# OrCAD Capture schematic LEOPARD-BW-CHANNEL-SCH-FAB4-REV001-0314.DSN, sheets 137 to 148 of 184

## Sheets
137 026_CPU1 - DDR4 (CHANNEL A): size A3; title: CPU1 - DDR4 (CHANNEL A)
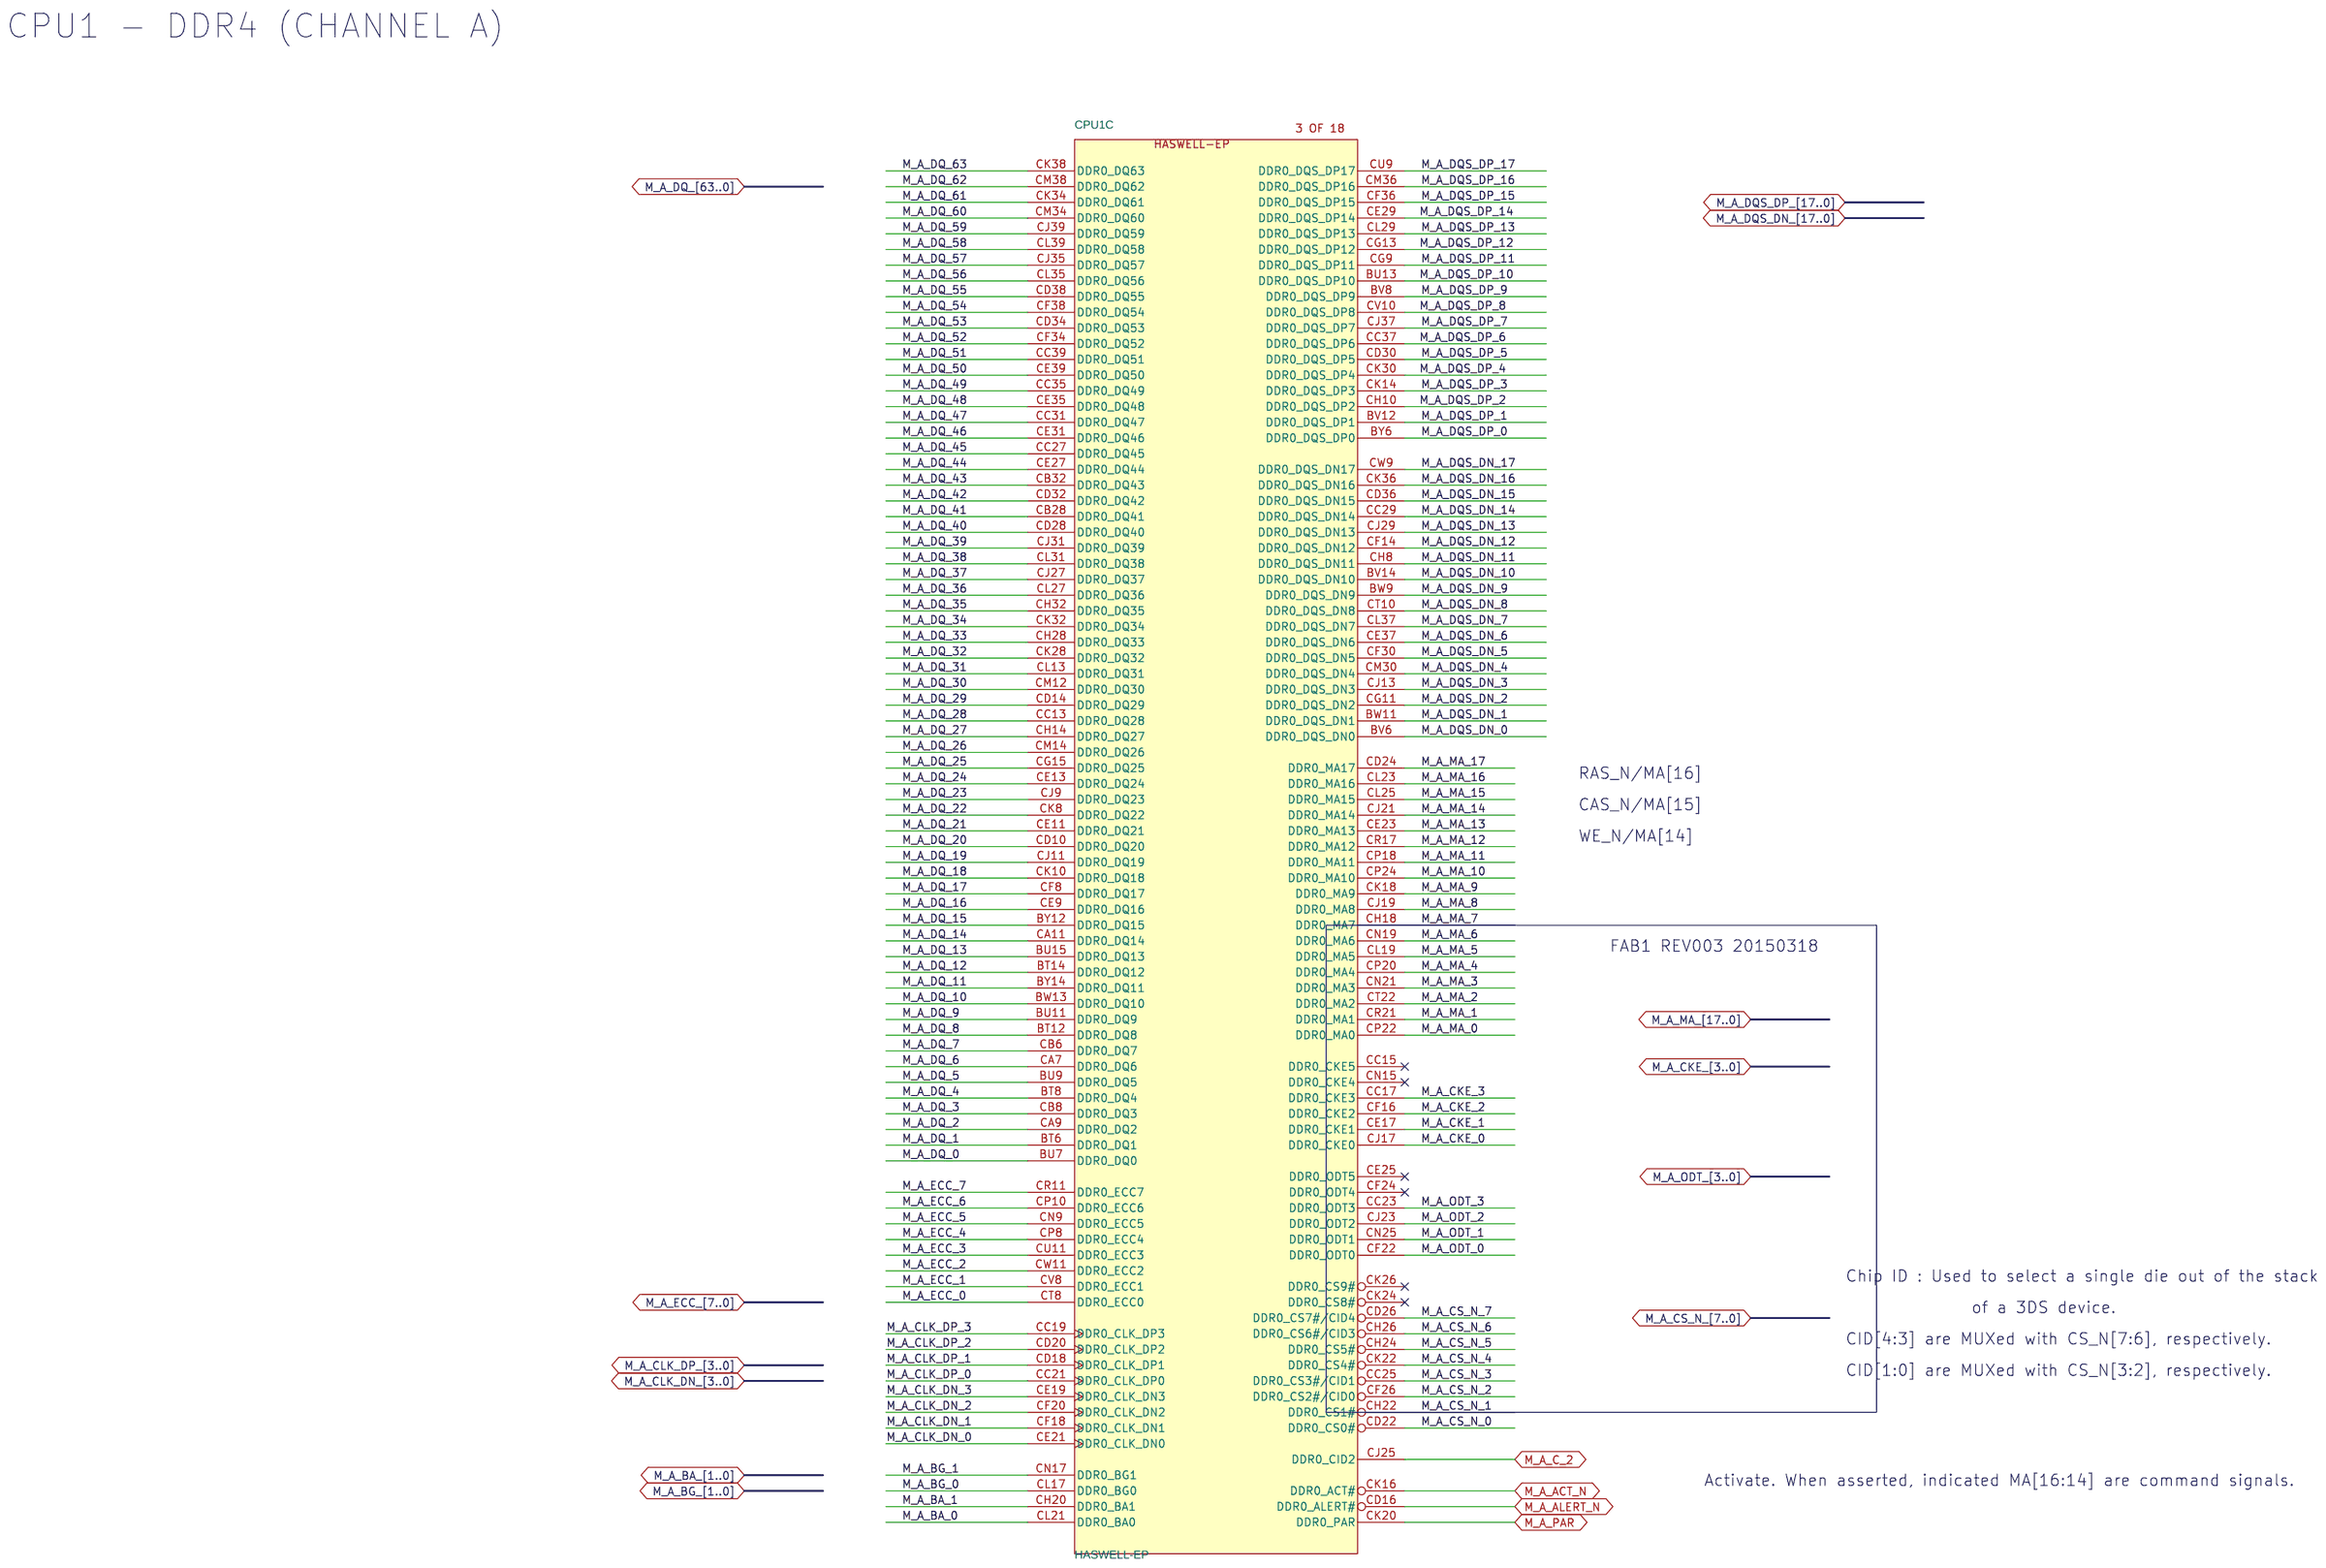
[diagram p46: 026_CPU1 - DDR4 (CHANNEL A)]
138 025_CPU1 - RESERVED PINS: size A3; title: CPU1 - RESERVED PINS
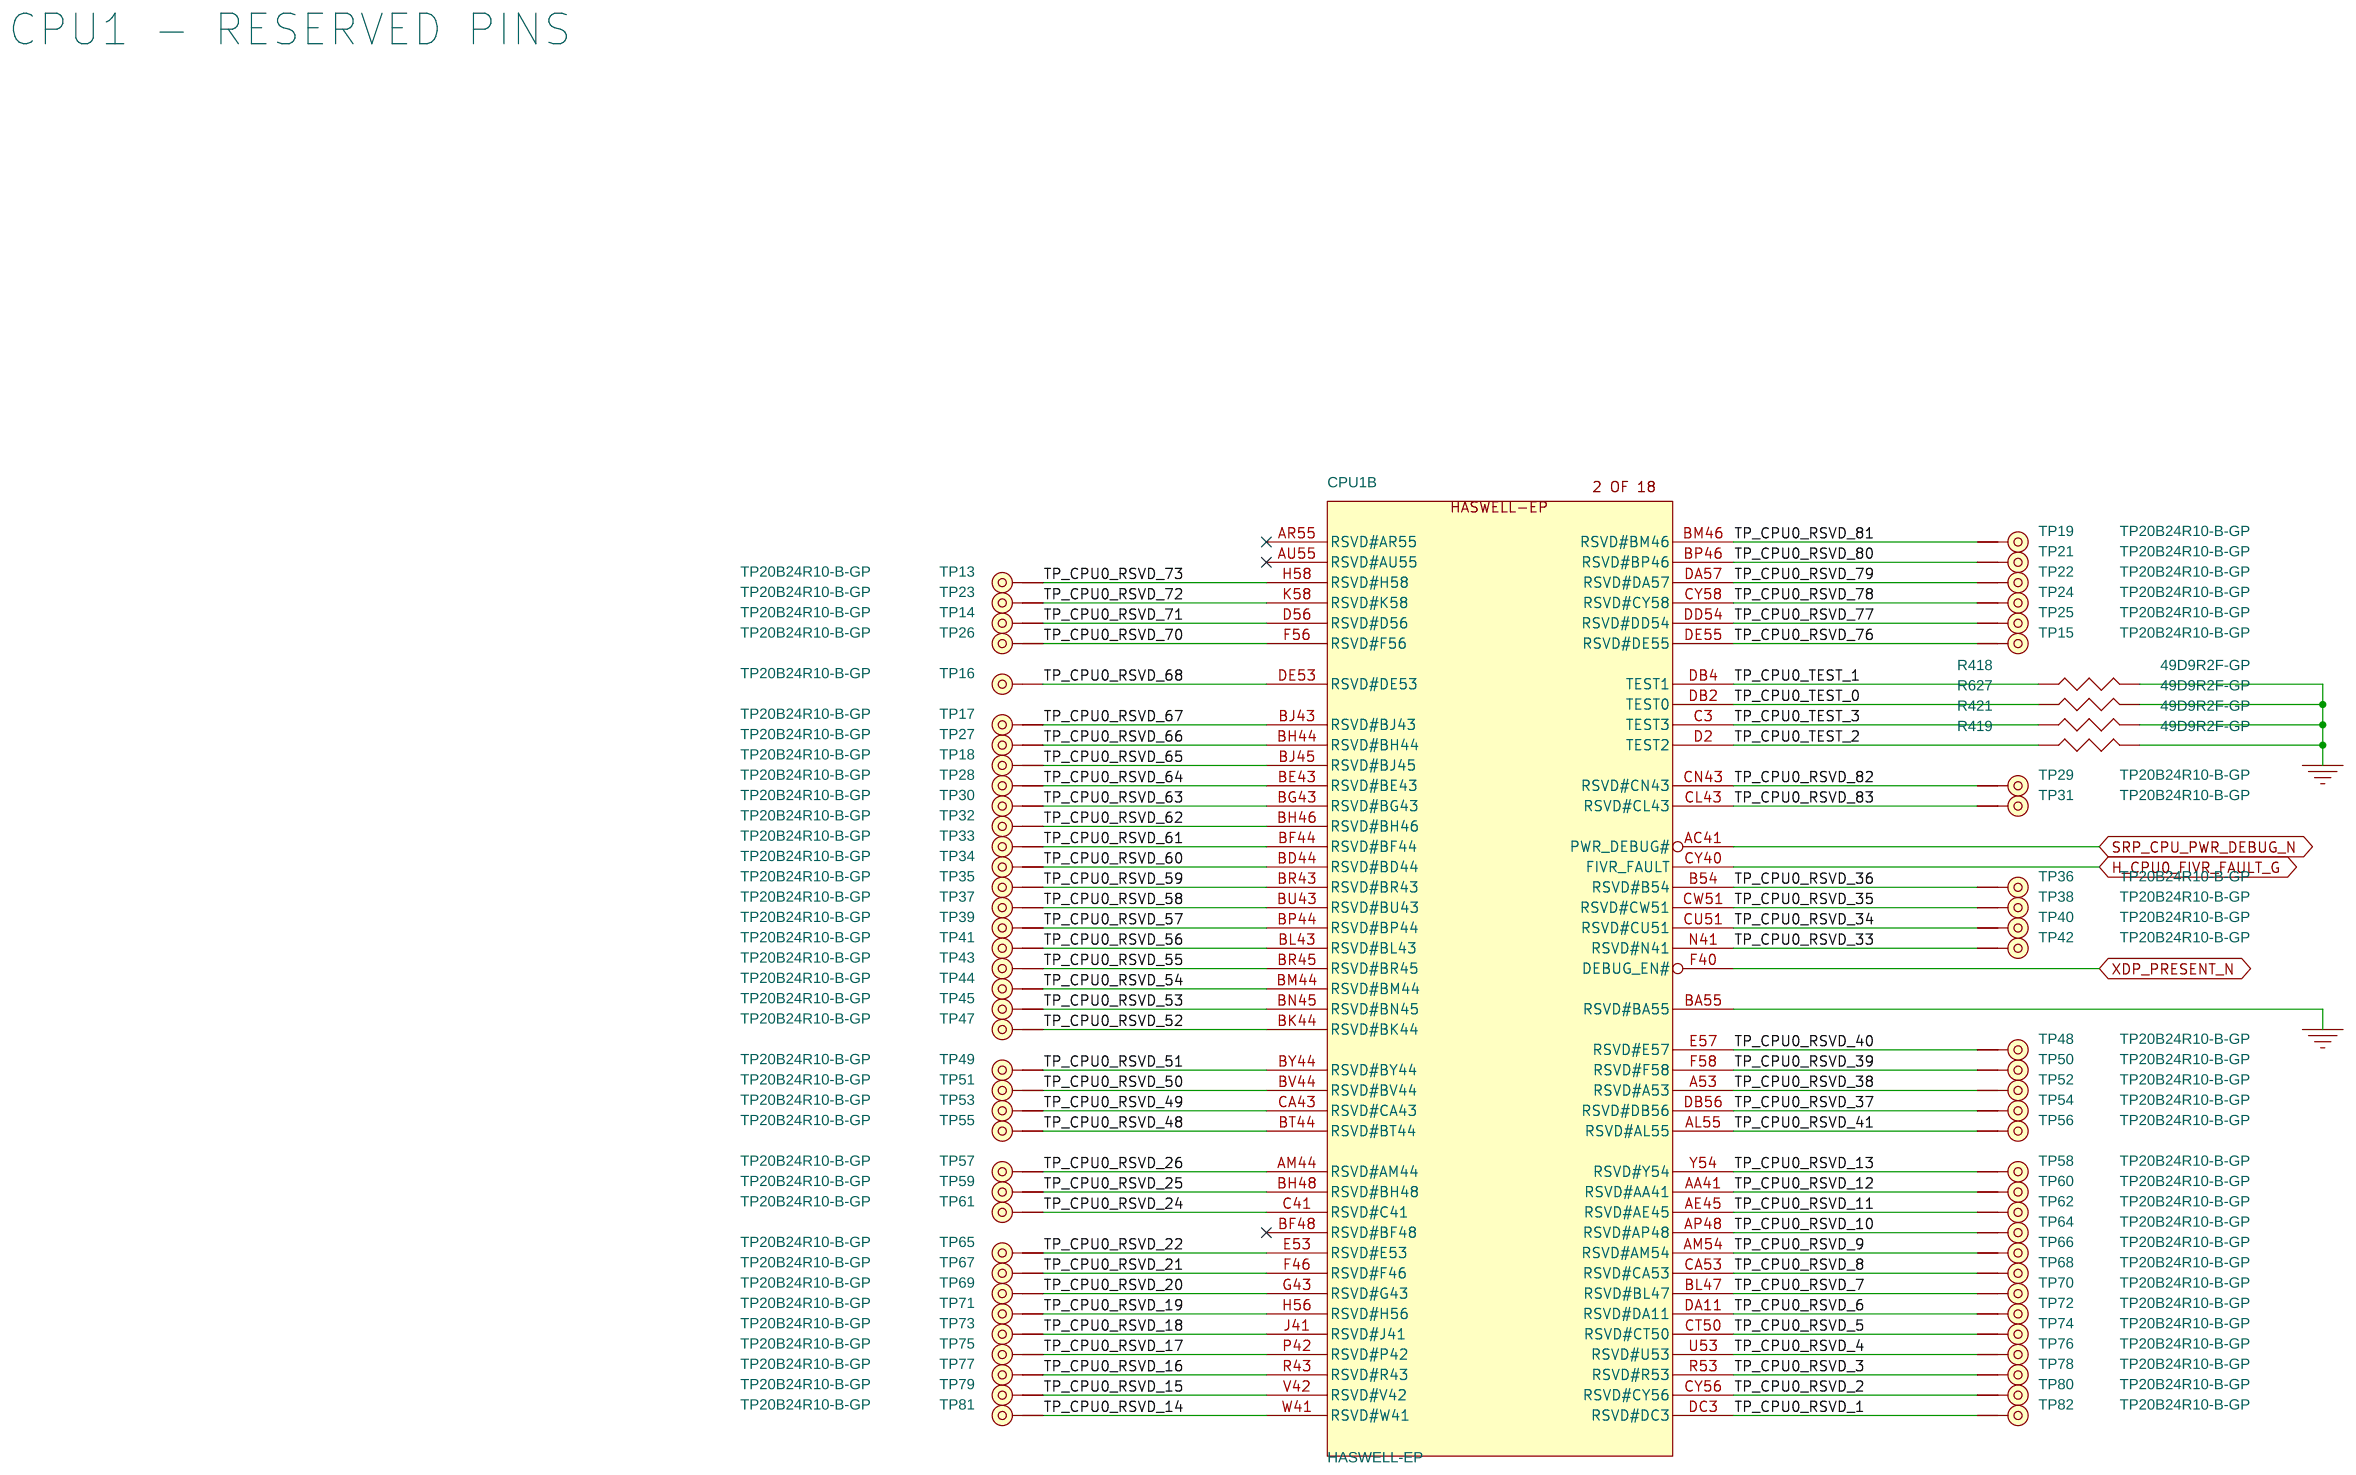
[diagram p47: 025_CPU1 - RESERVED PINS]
139 024_CPU1 - MICS: size A3; title: CPU1 - MICS
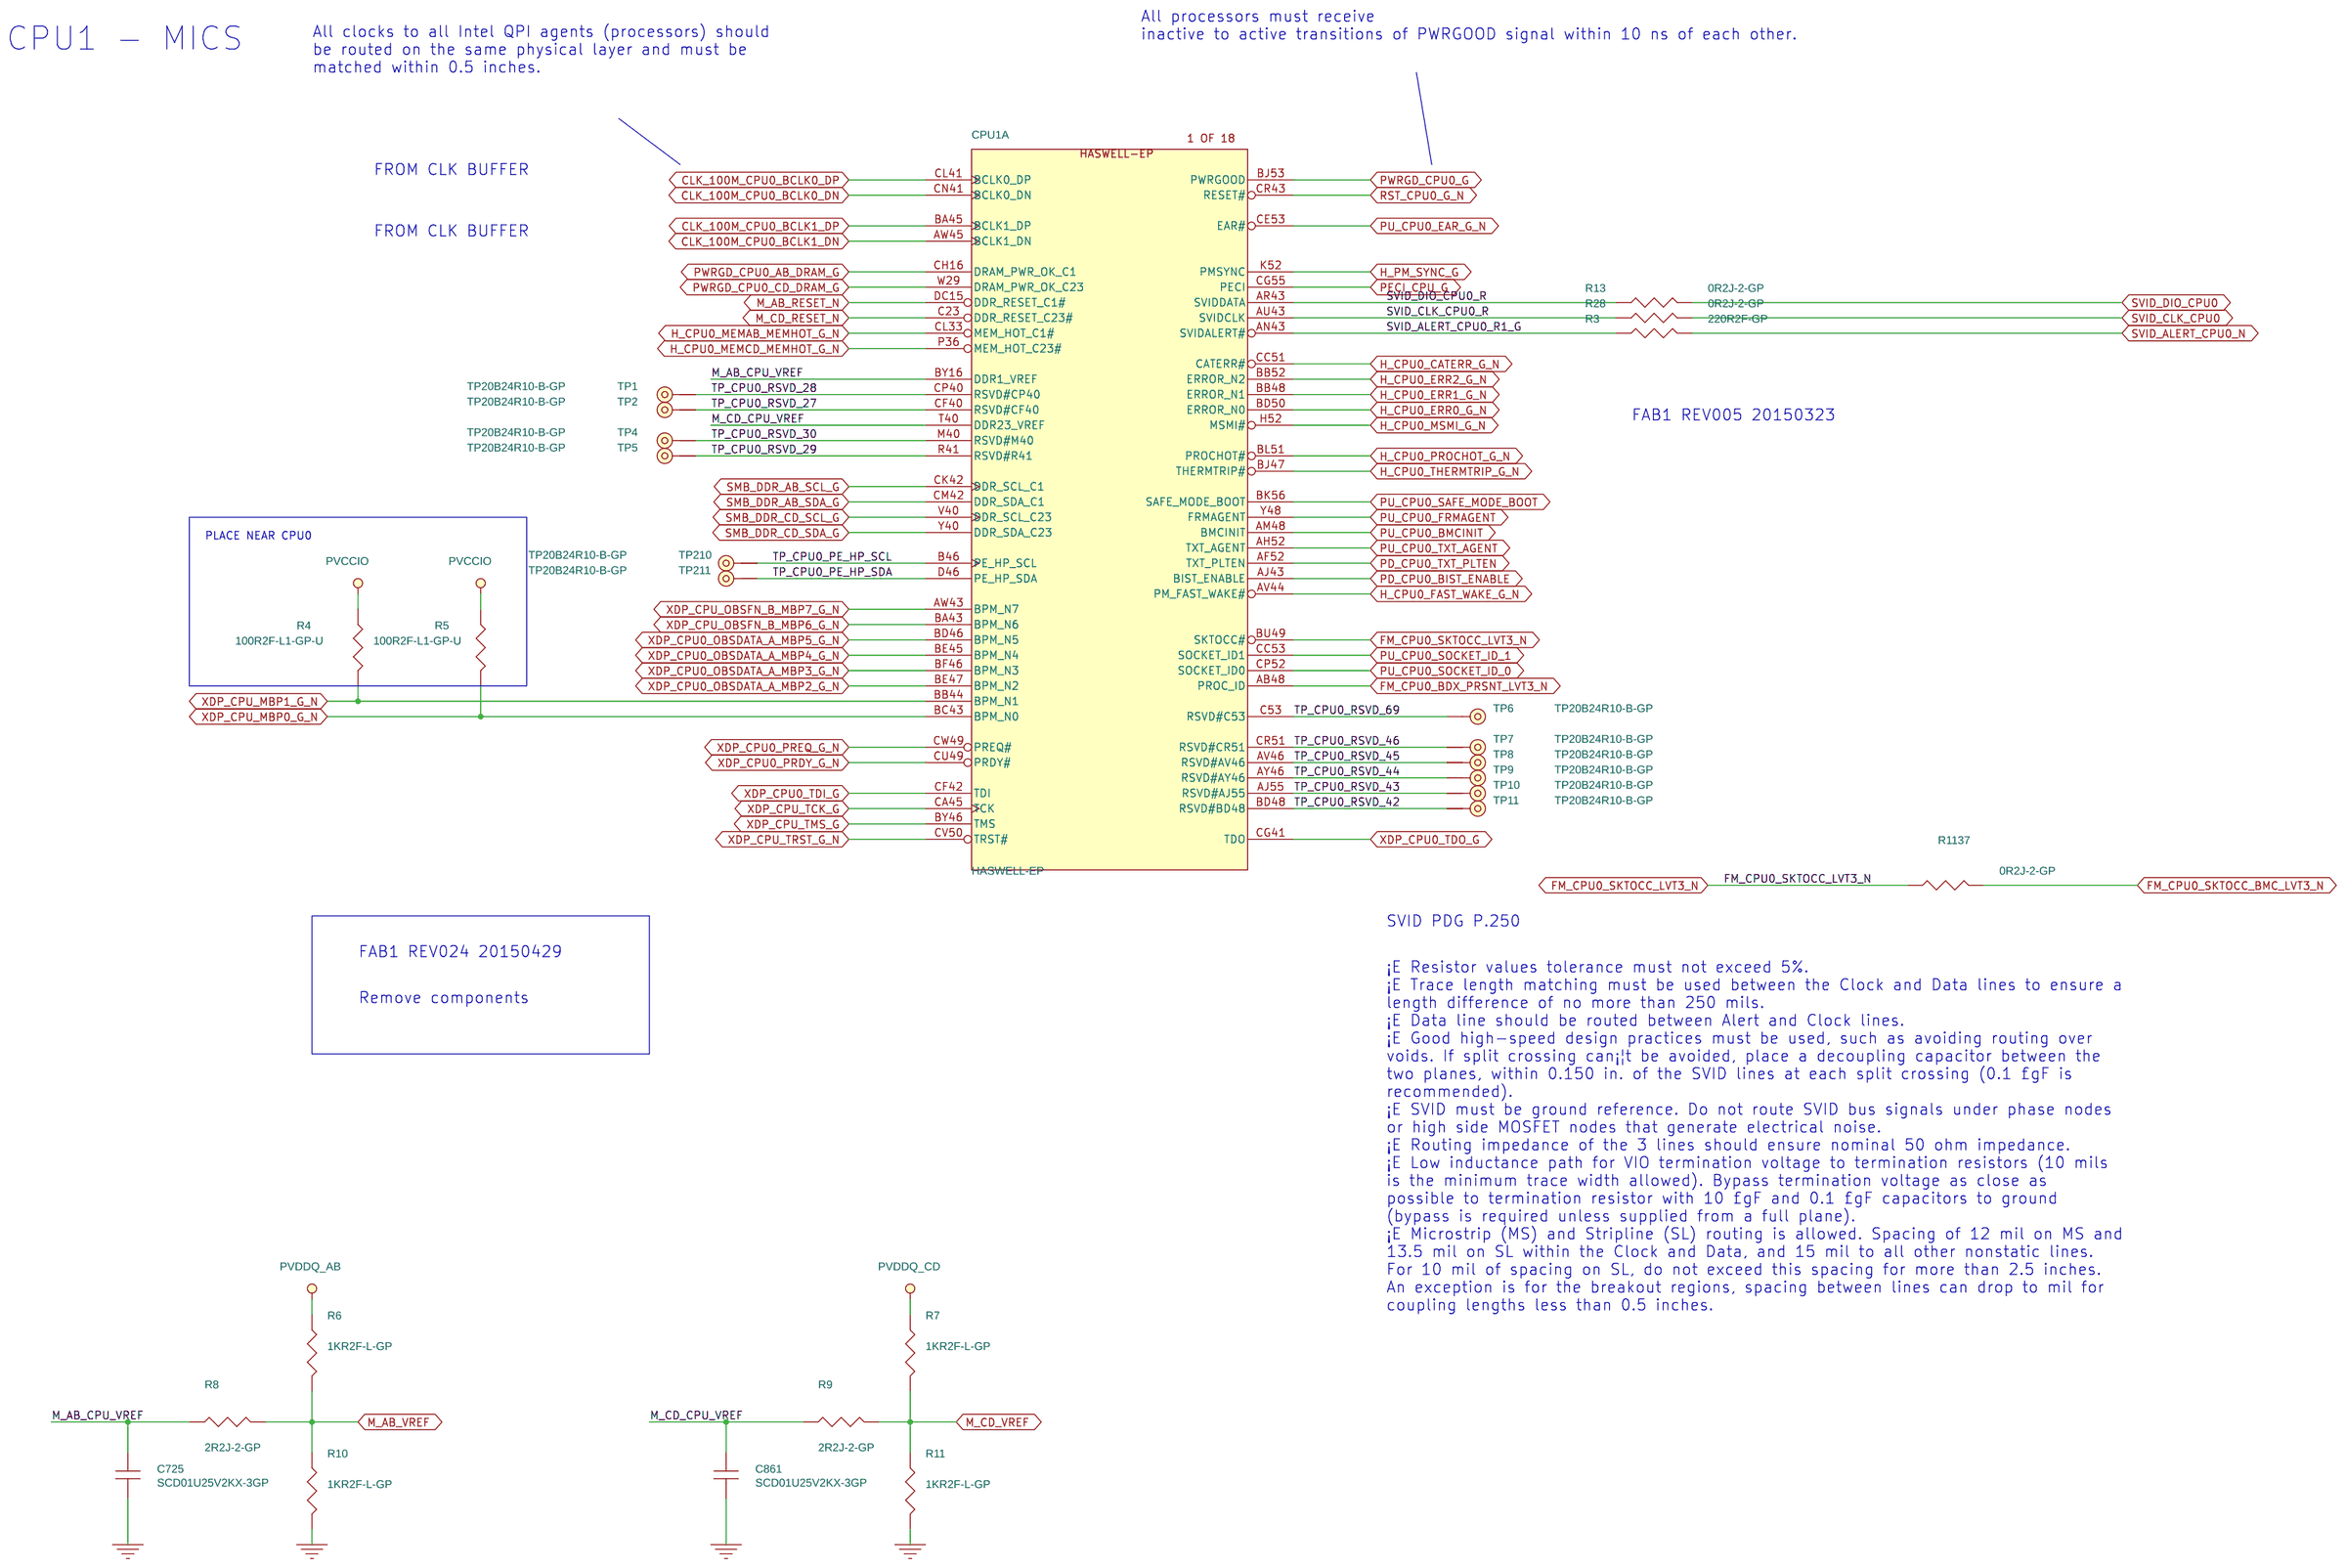
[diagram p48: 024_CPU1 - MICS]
140 023_NVDIMM BLOCK DIAGRAM: title: NVDIMM BLOCK DIAGRAM
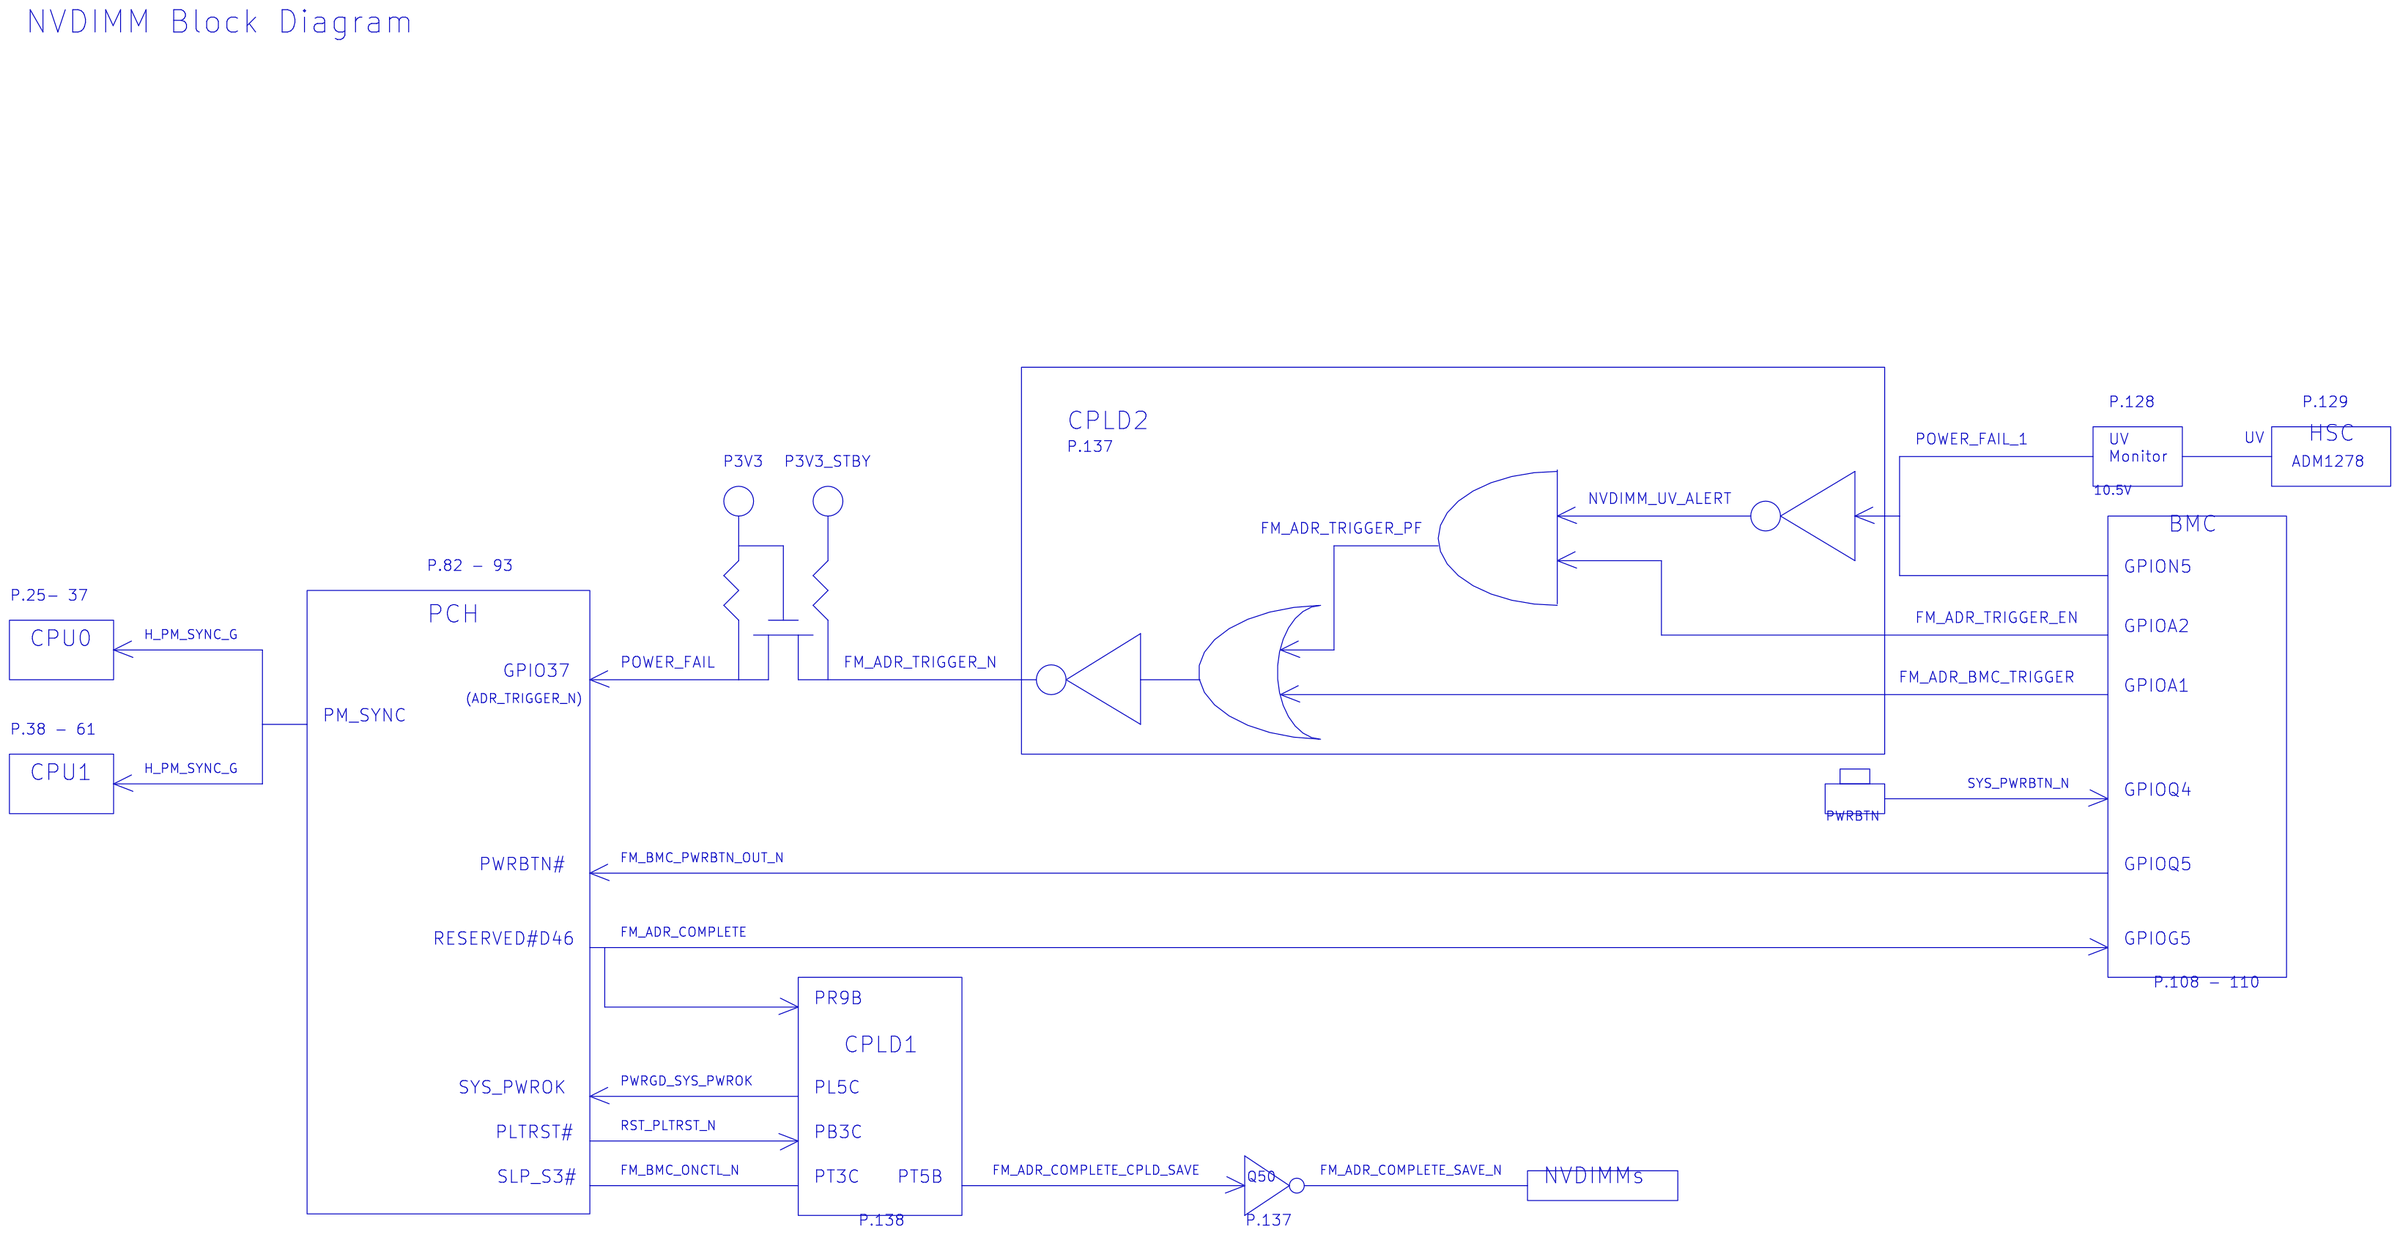
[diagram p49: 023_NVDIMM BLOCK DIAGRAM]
141 022_JTAG BLOCK DIAGRAM: title: JTAG BLOCK DIAGRAM
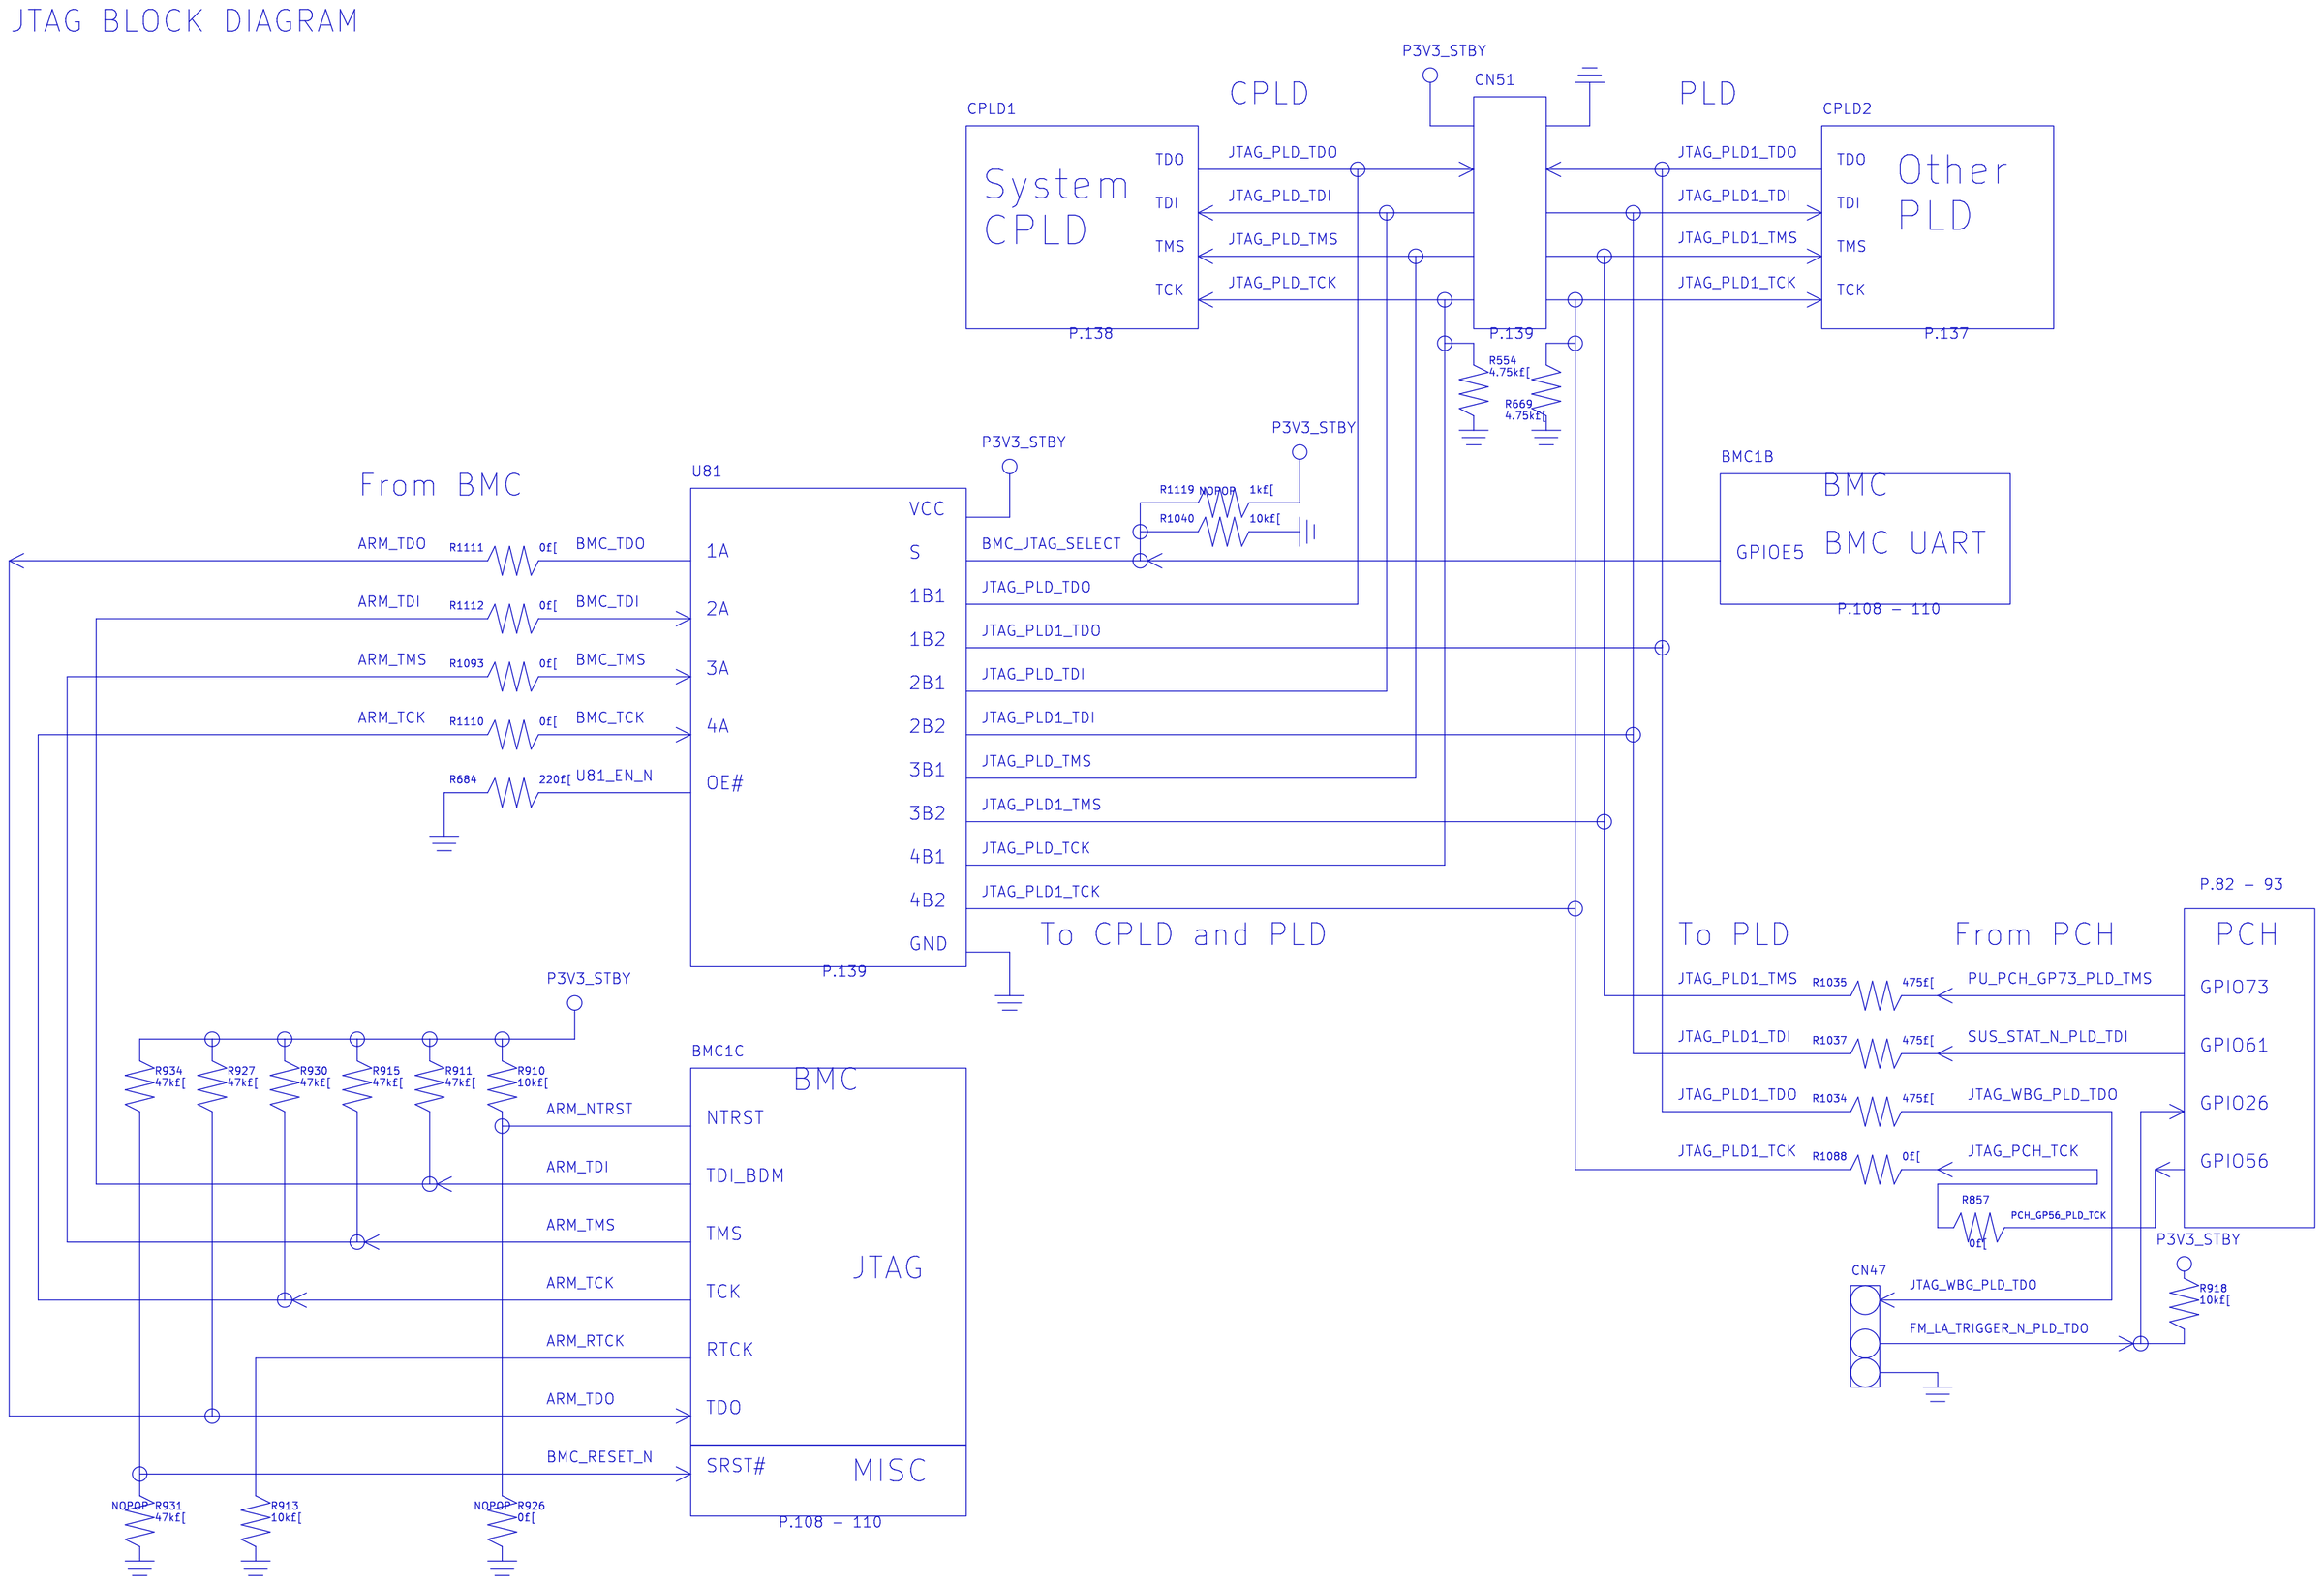
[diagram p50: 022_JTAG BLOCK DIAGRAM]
142 021_POWER SEQUENCE DIAGRAM: title: POWER SEQUENCE DIAGRAM
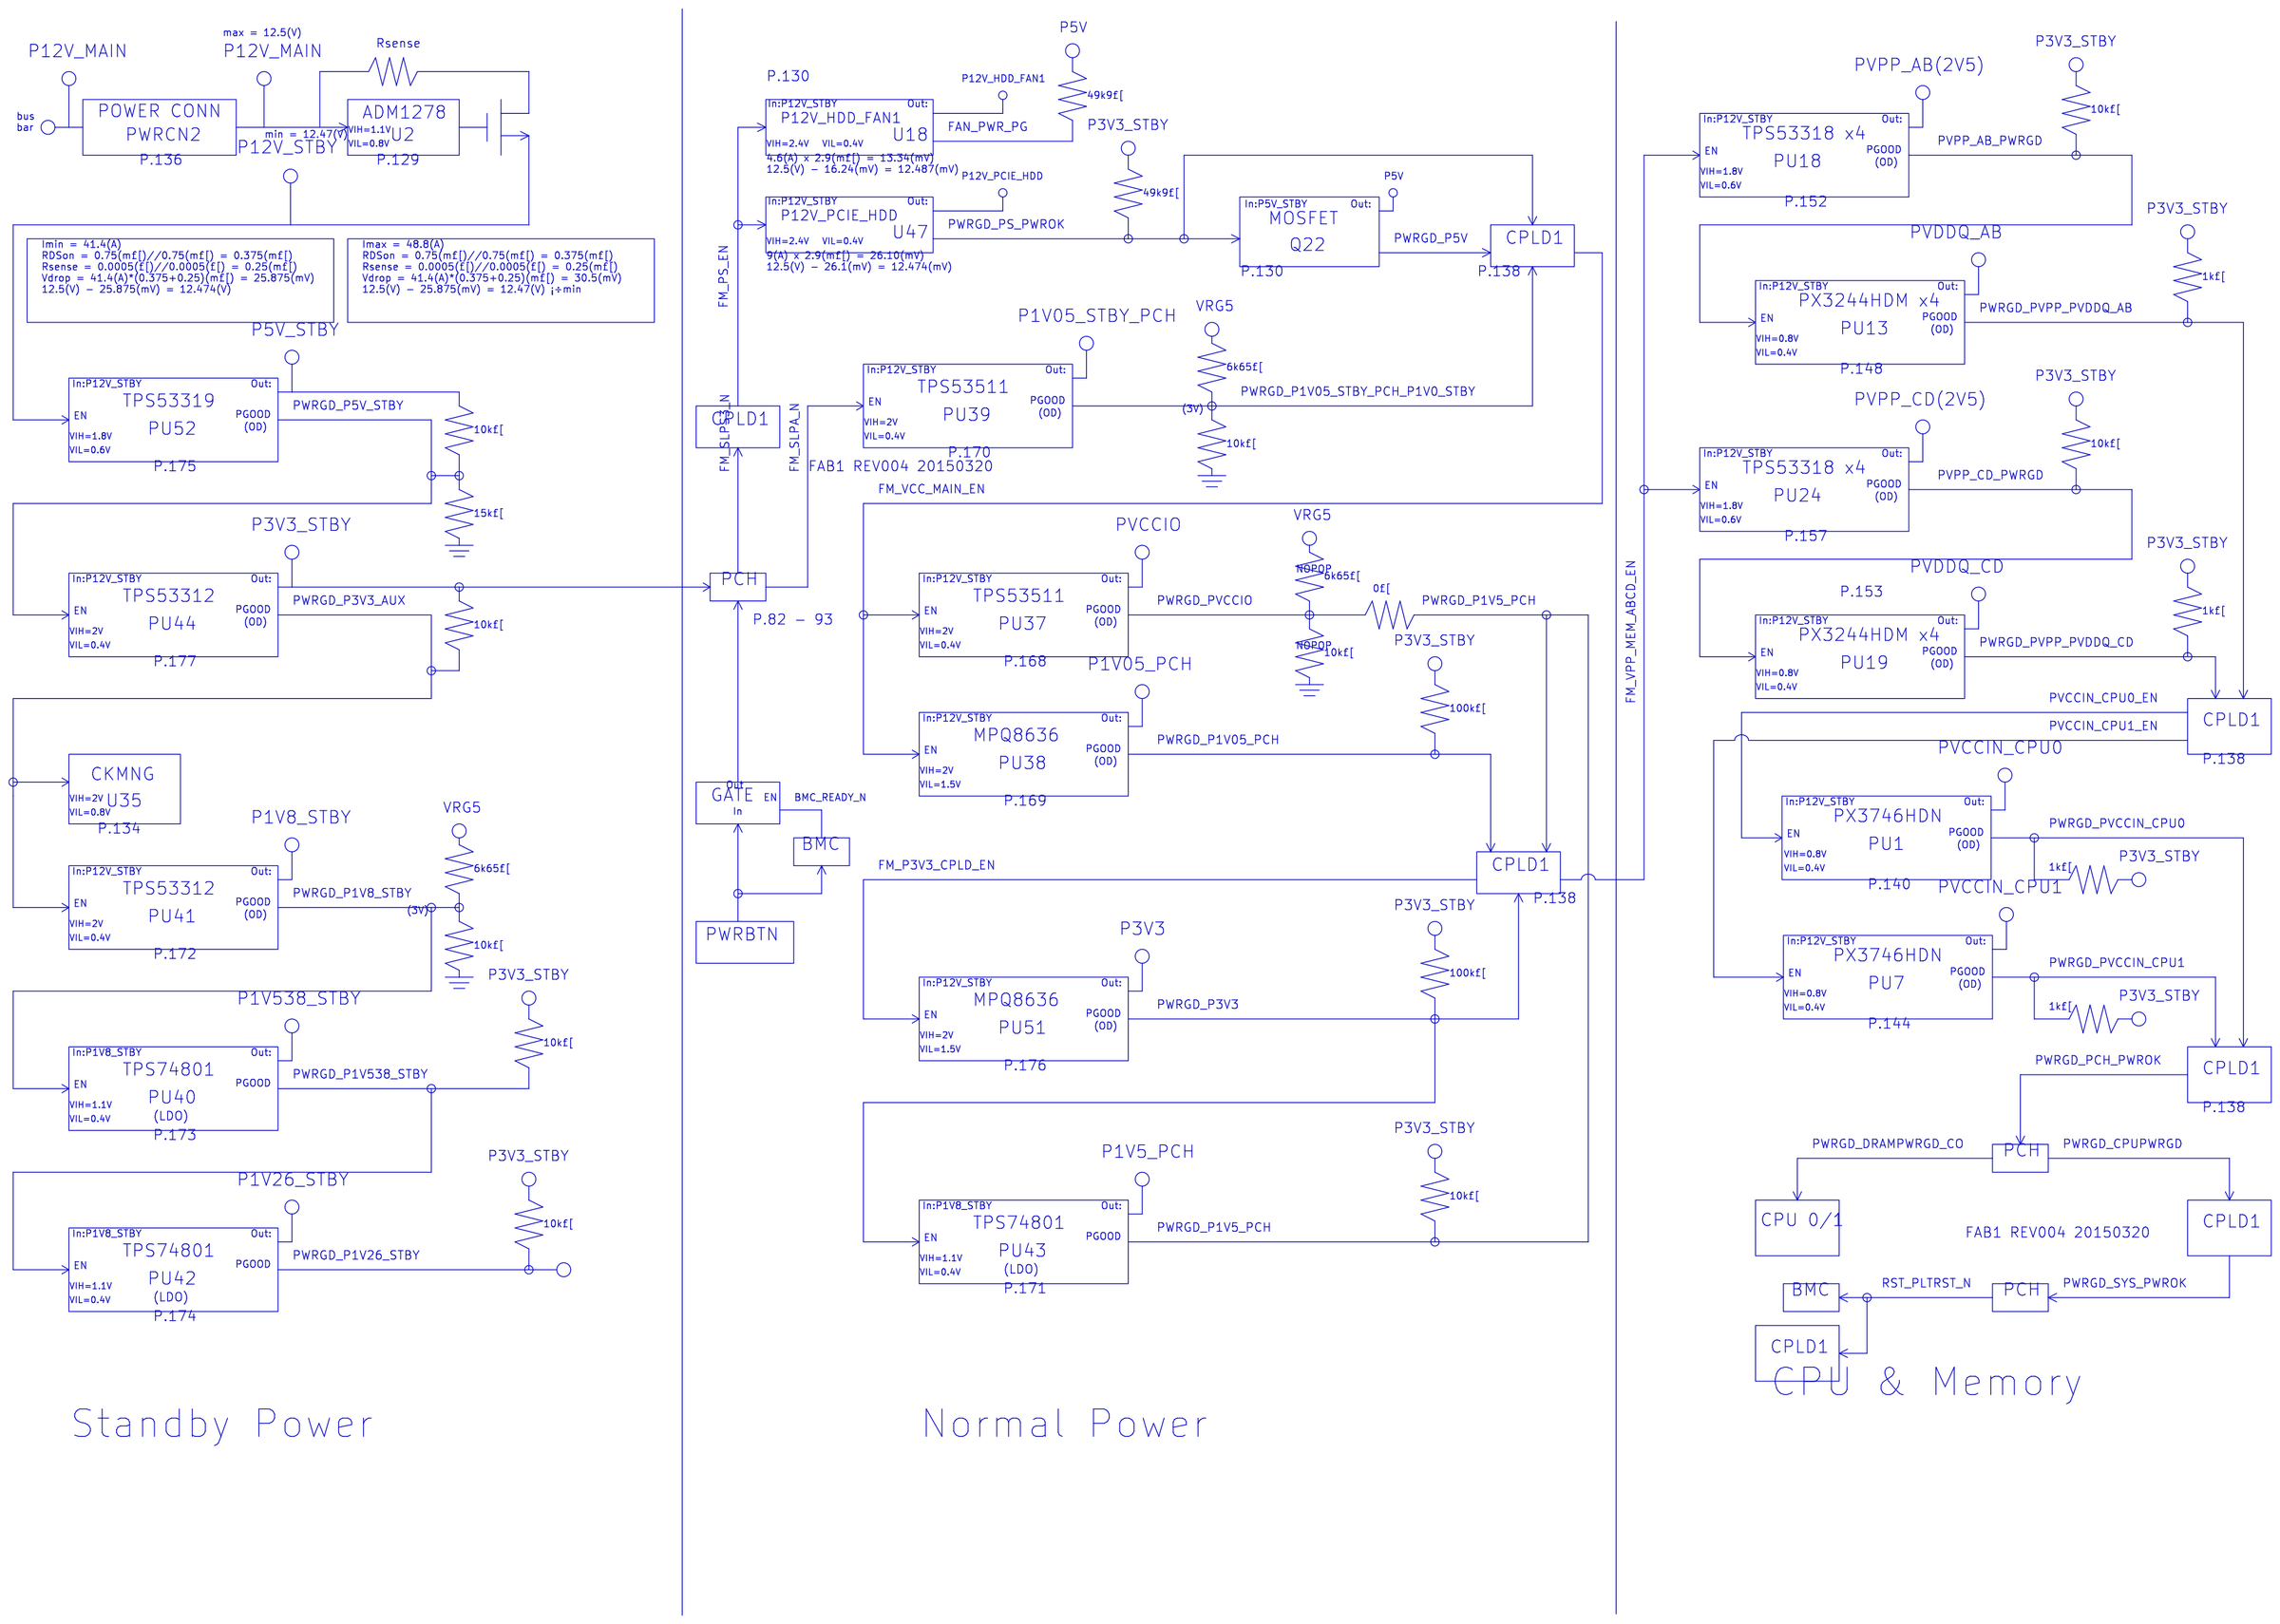
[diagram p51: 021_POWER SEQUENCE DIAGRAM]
143 020_BIOS-SPI SWITCH DIAGRAM: title: BIO-SPI SWITCH DIAGRAM
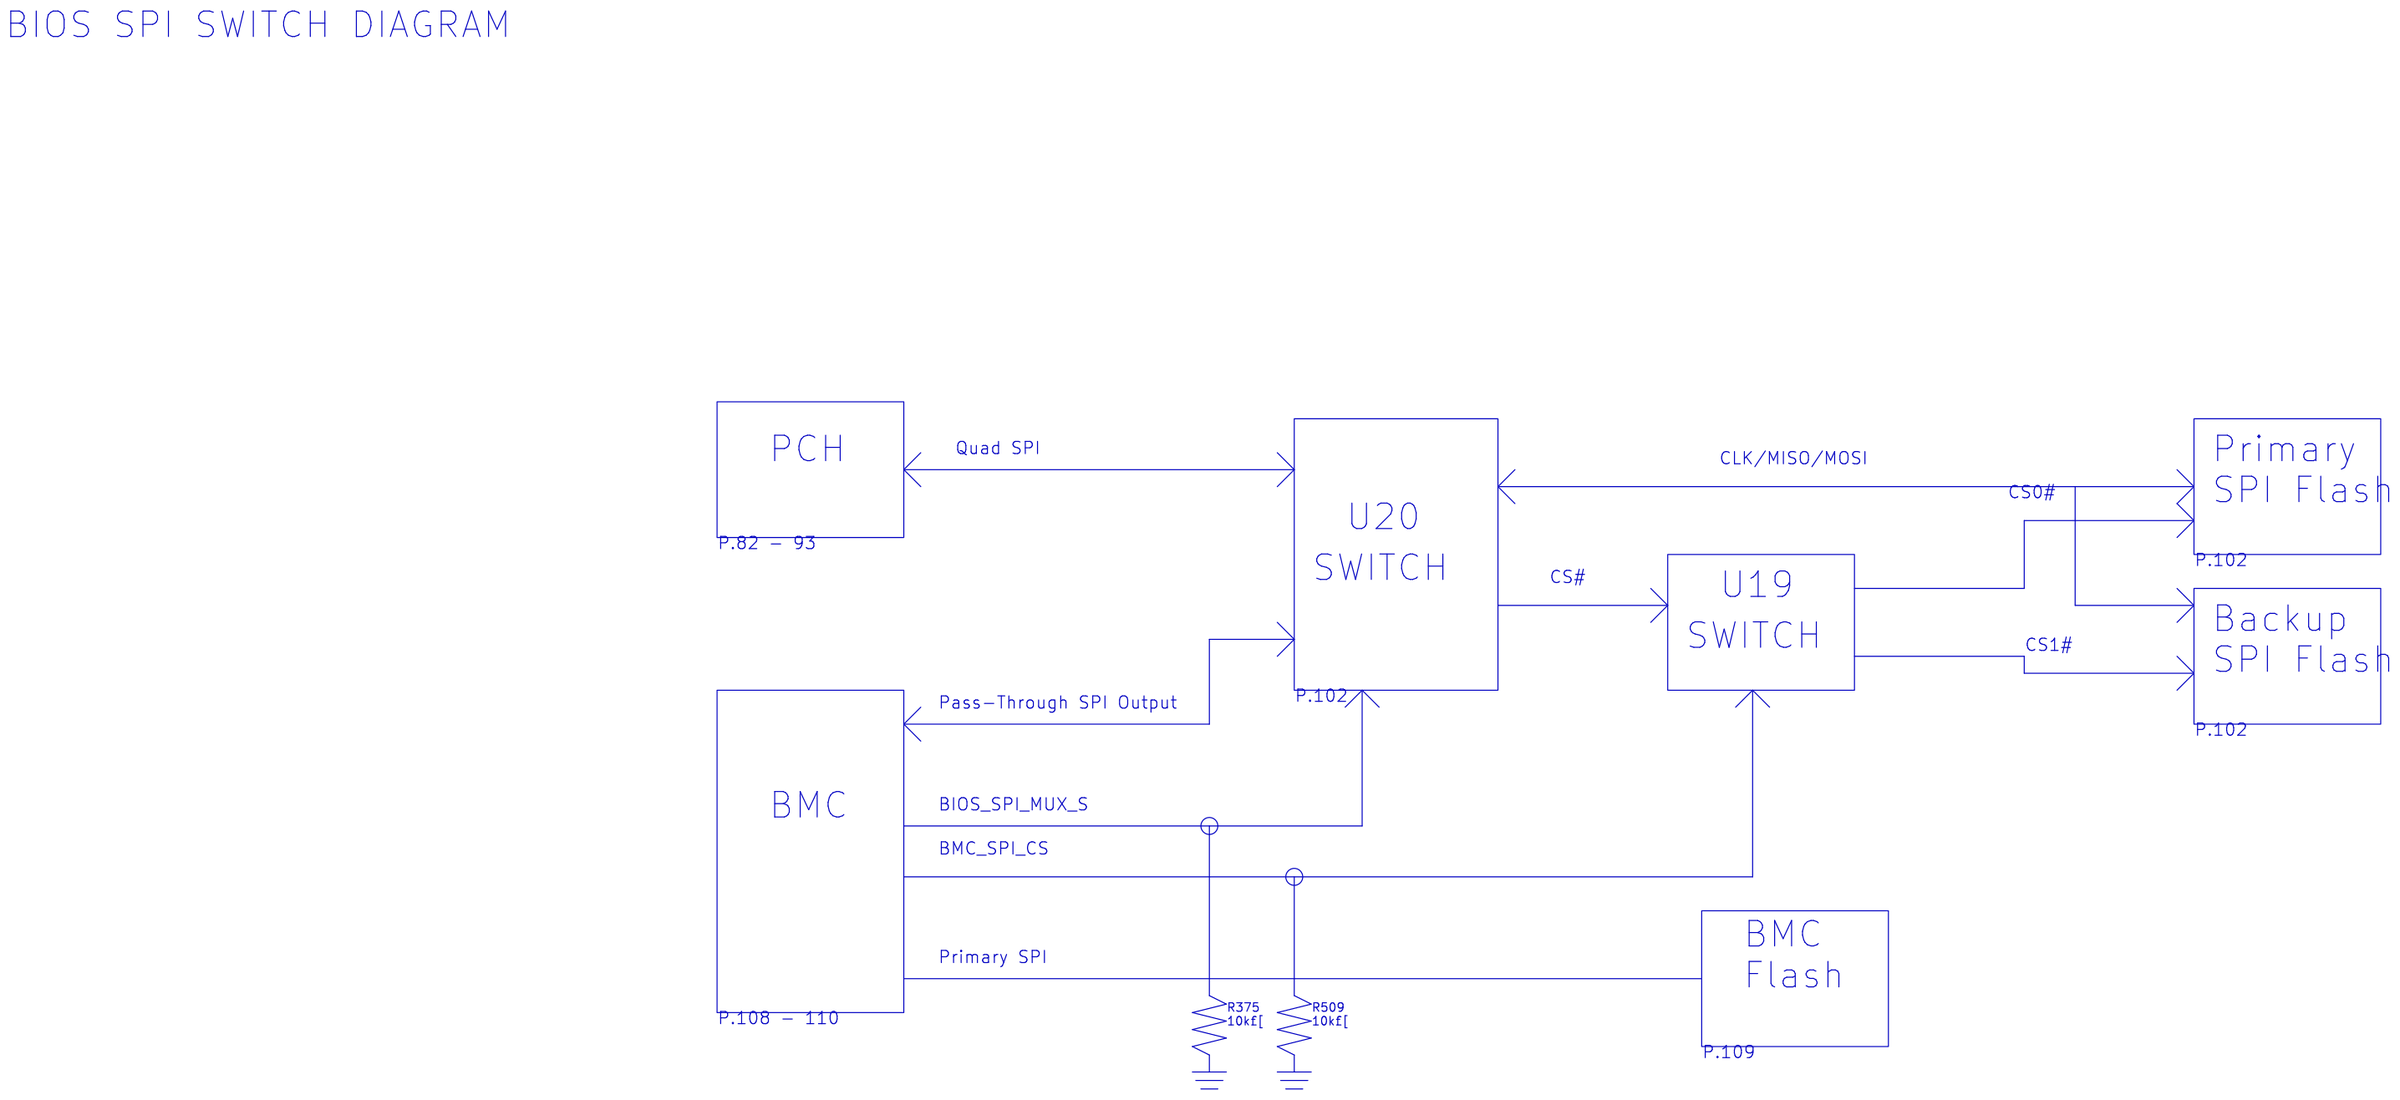
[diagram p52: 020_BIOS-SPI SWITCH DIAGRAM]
144 019_UART SEL BLOCK DIAGRAM: title: UART SEL BLOCK DIAGRAM
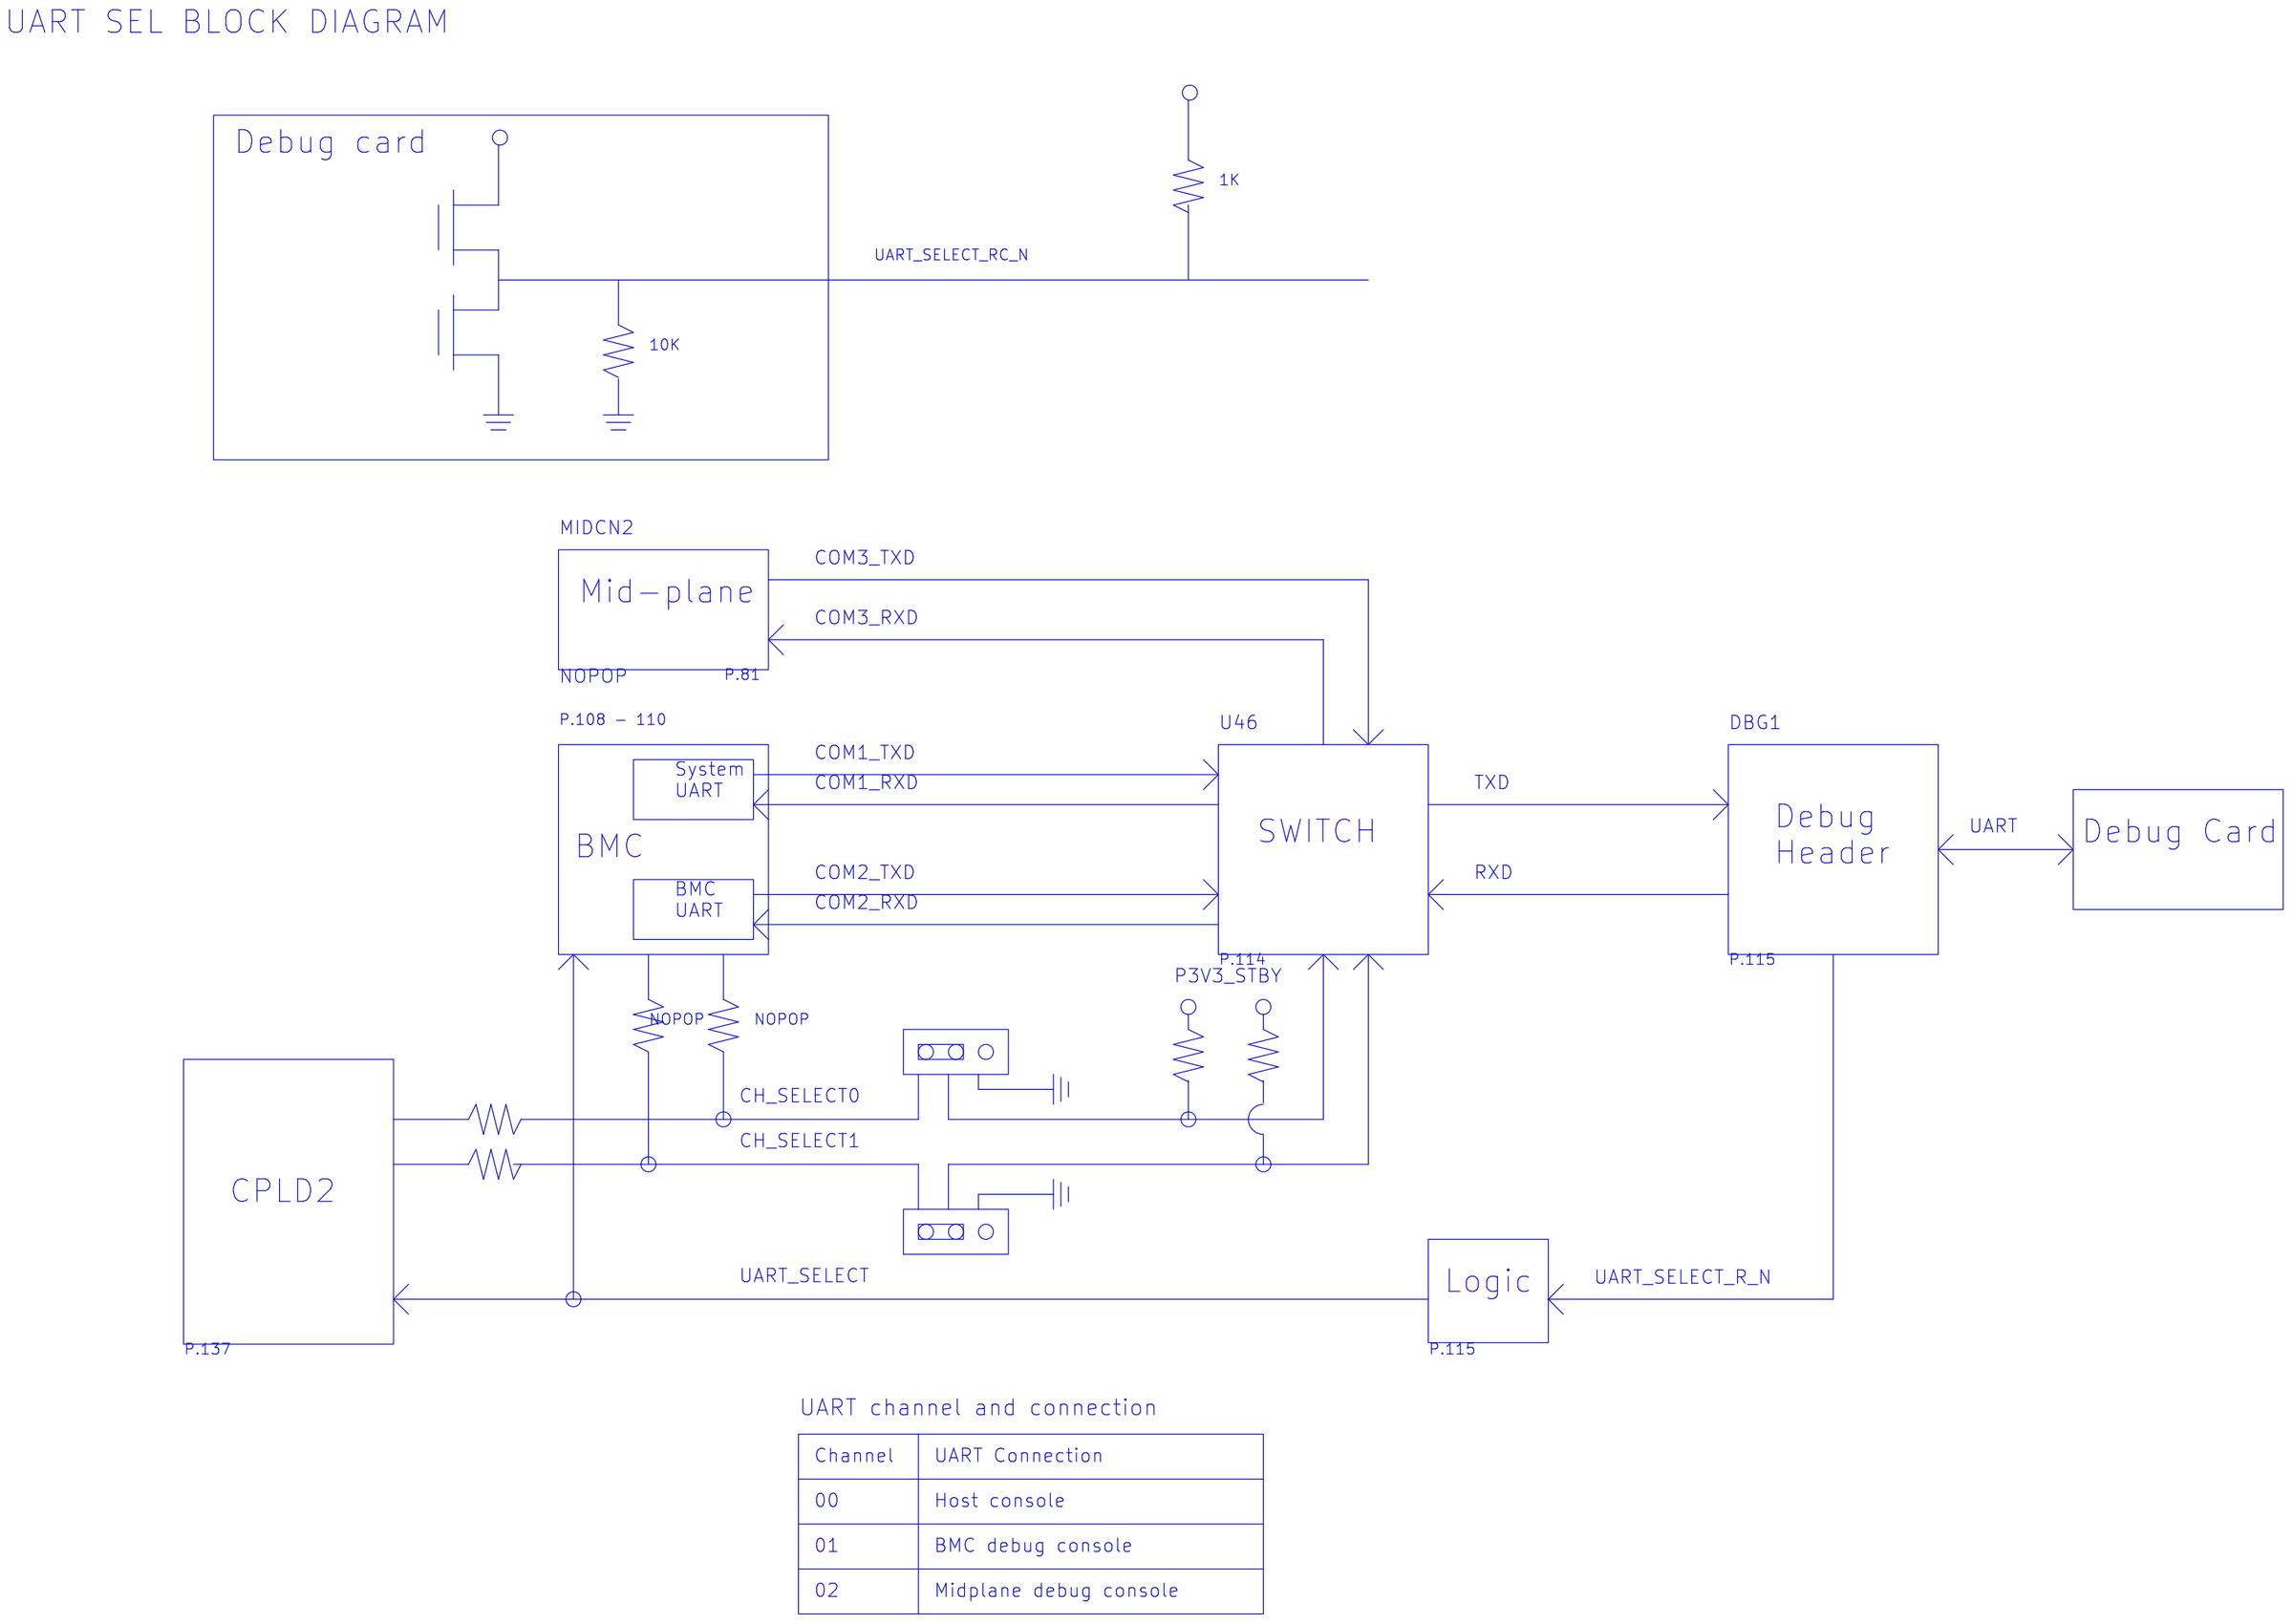
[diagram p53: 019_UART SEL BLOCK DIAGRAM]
145 018_DDR SETTING: title: DDR SETTING
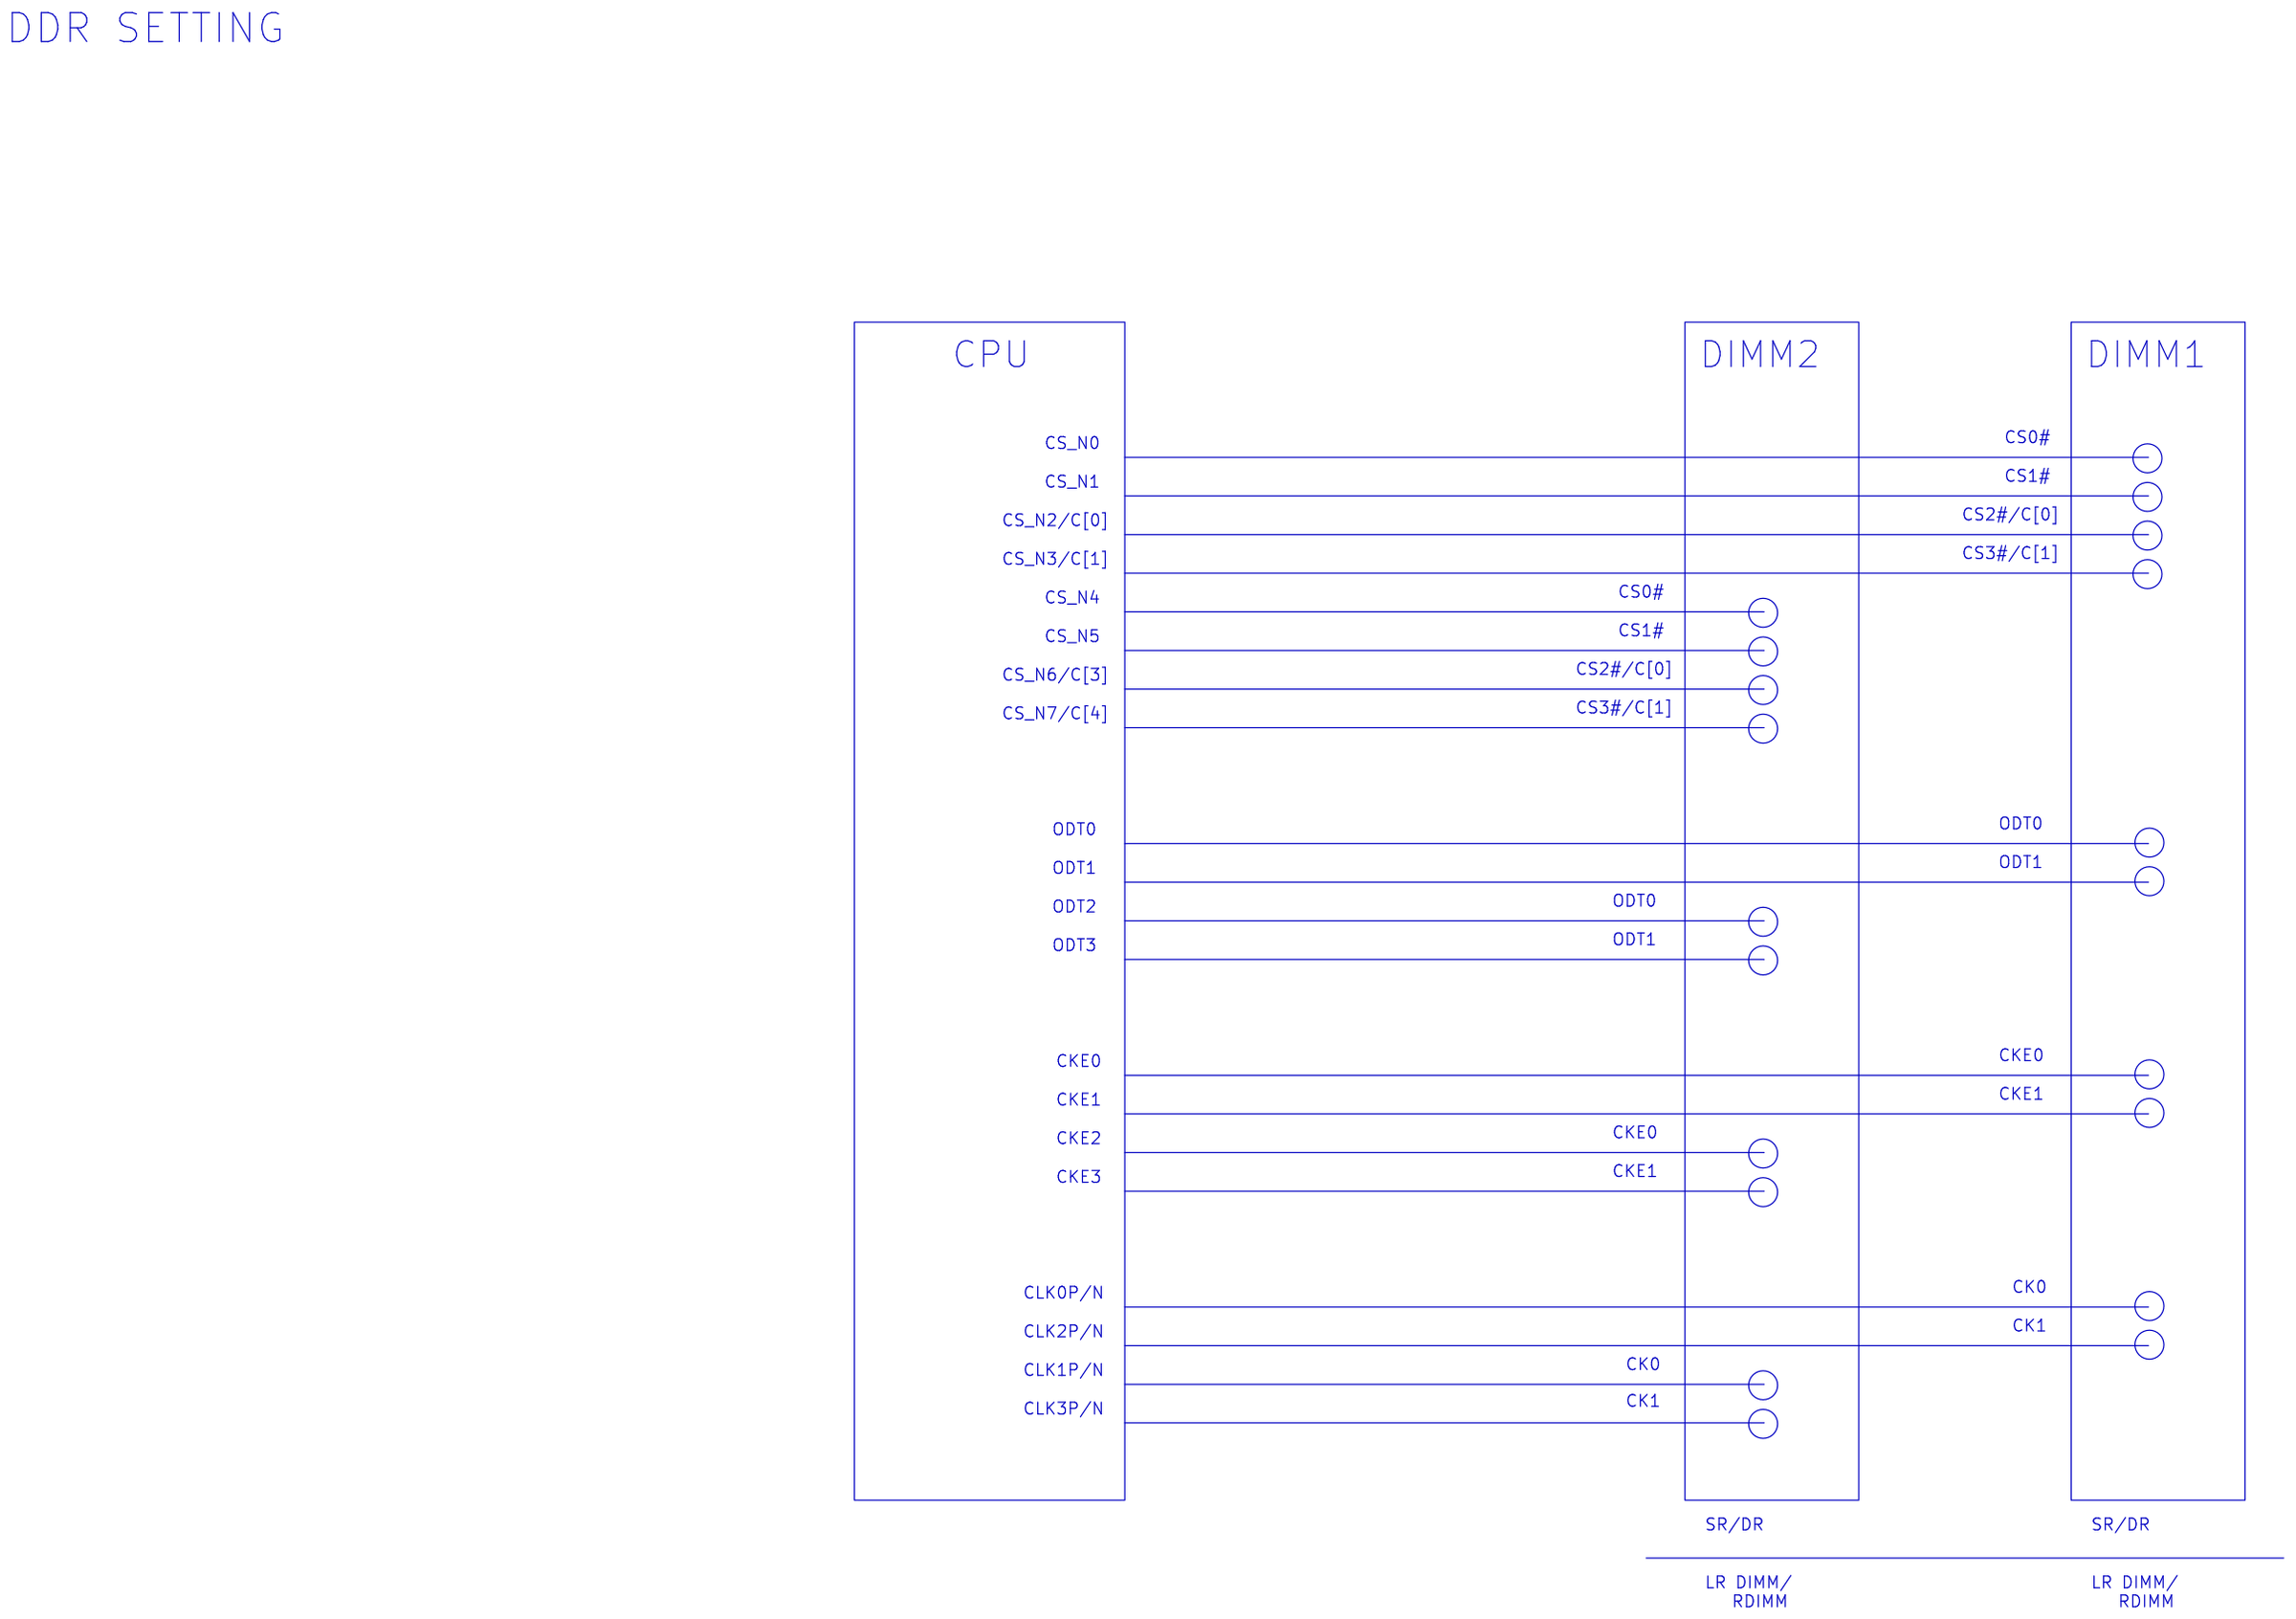
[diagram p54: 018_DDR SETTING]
146 017_PERIPHERAL BOARD DIAGRAM: title: PERIPHERAL BOARD DIAGRAM
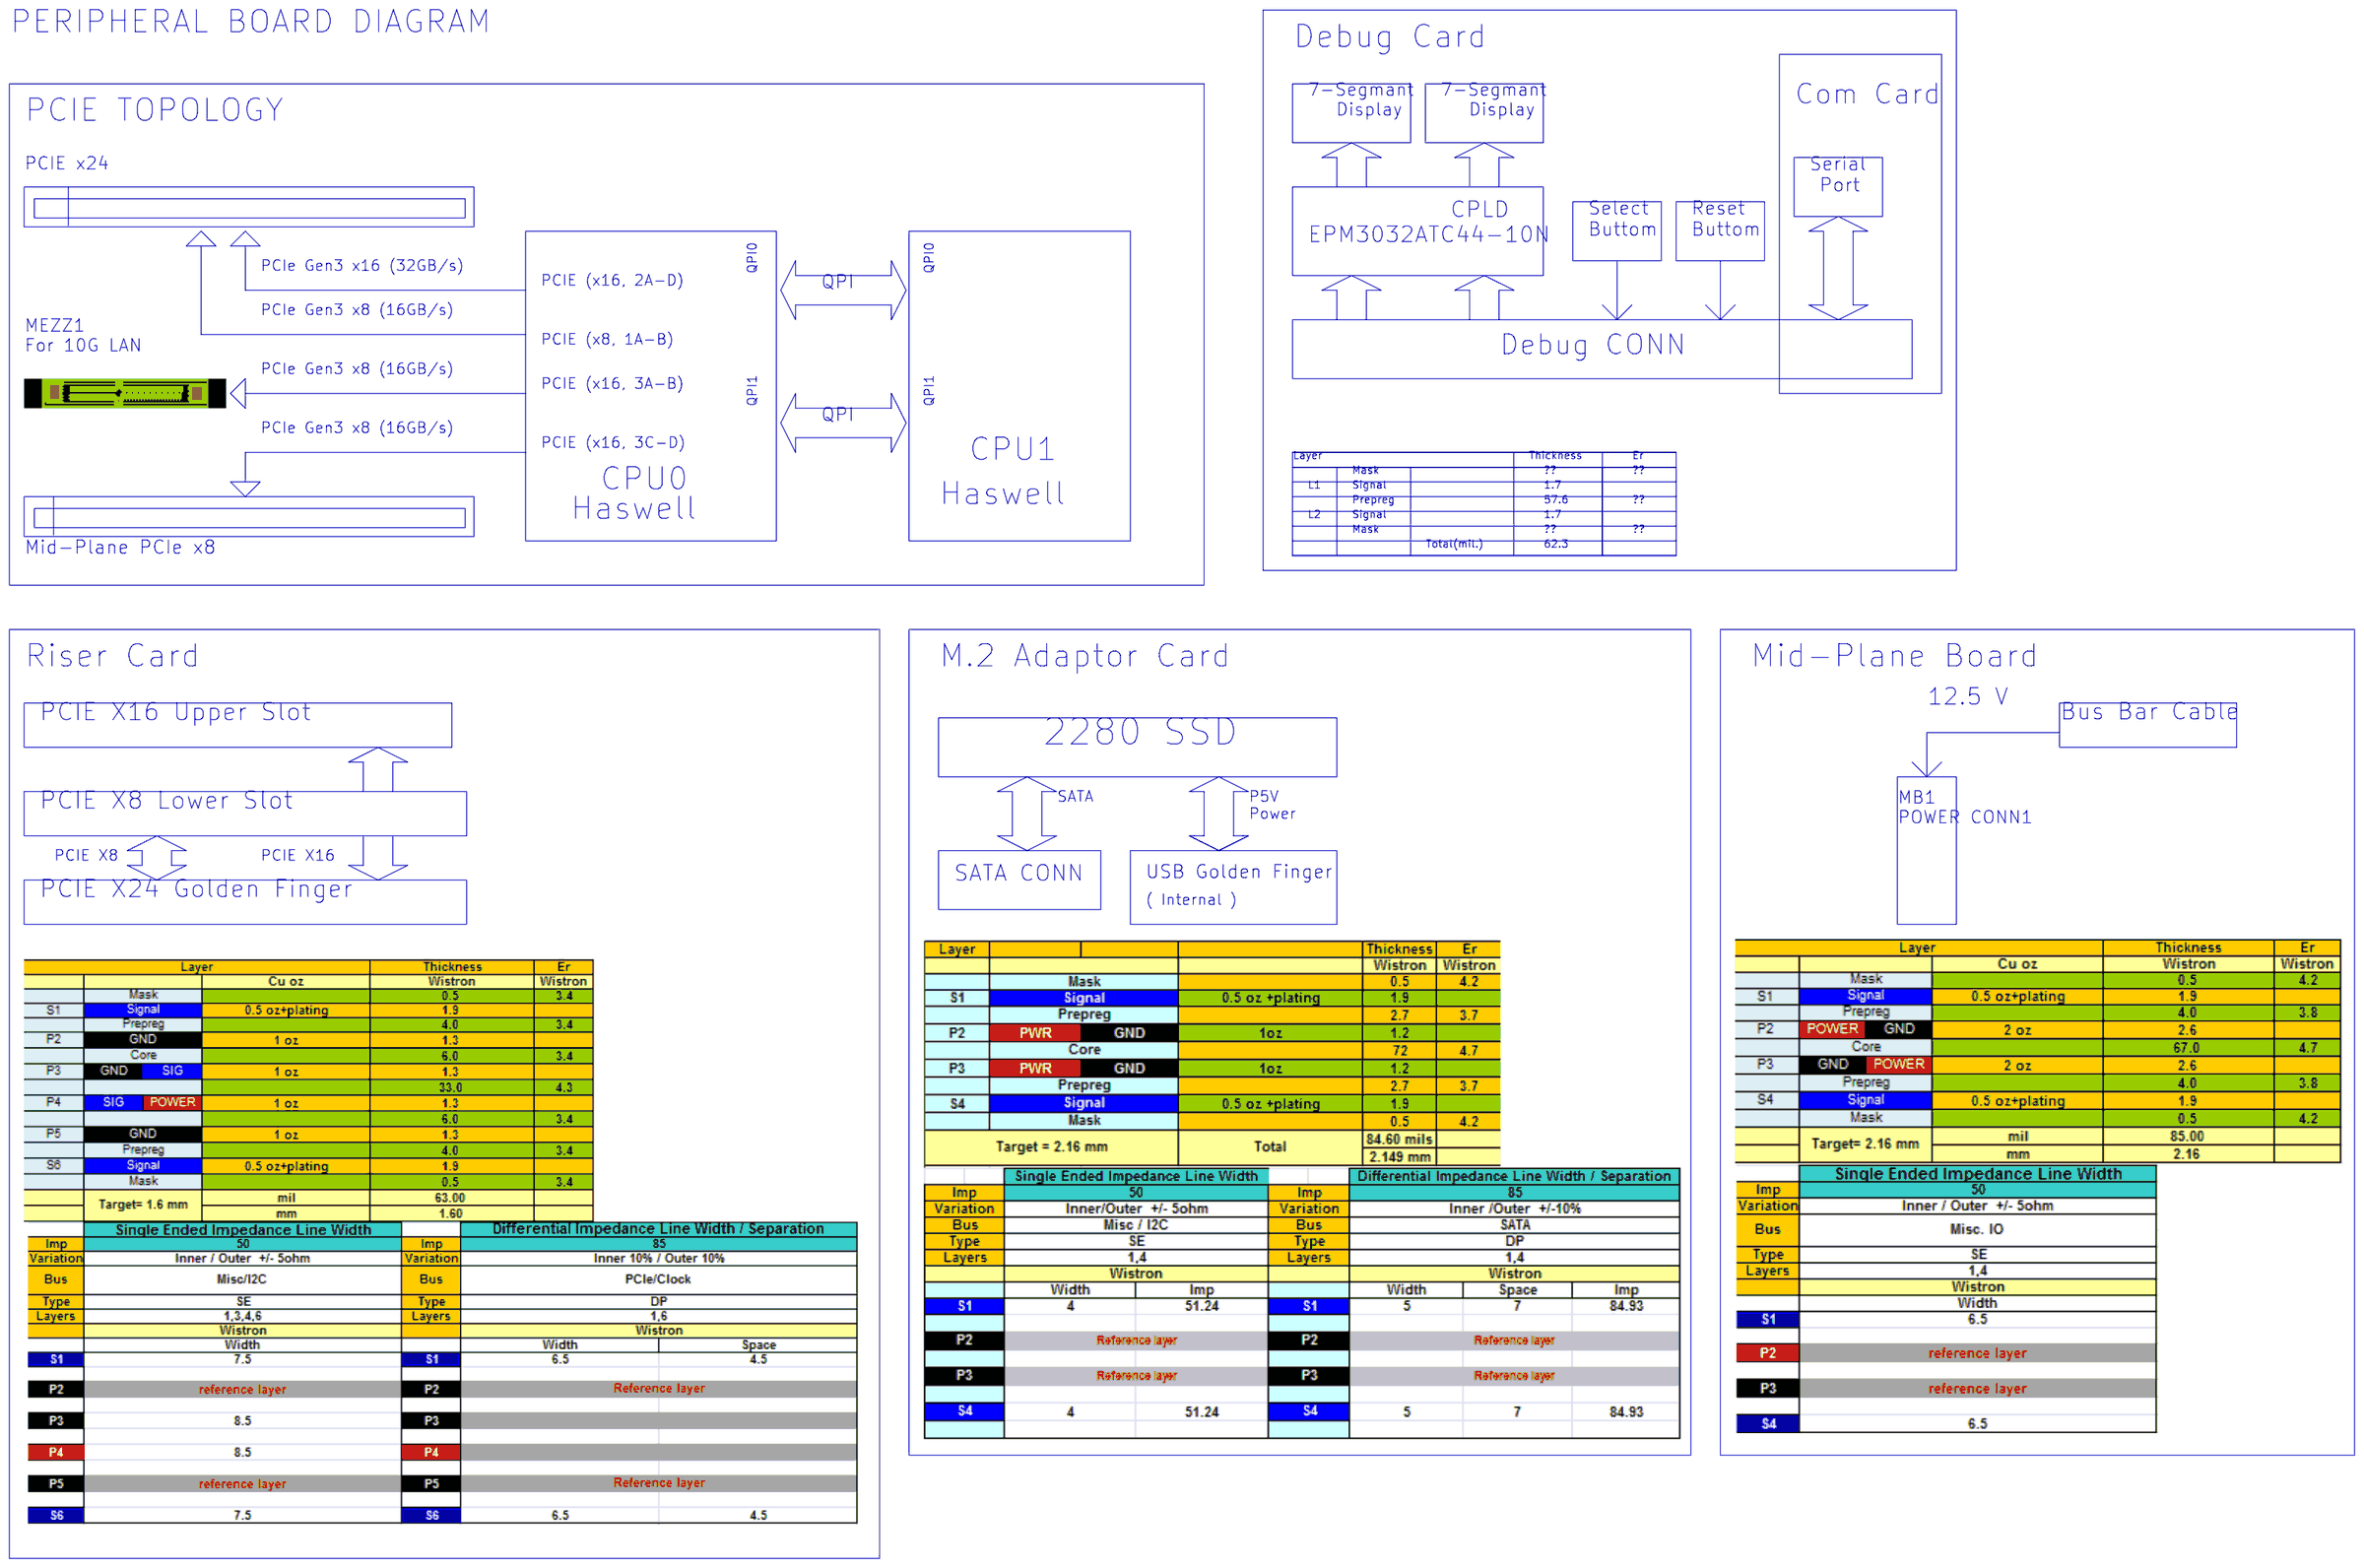
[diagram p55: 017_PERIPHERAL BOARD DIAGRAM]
147 016_HOT PLUG BLOCK DIAGRAM: title: HOT PLUG BLOCK DIAGRAM
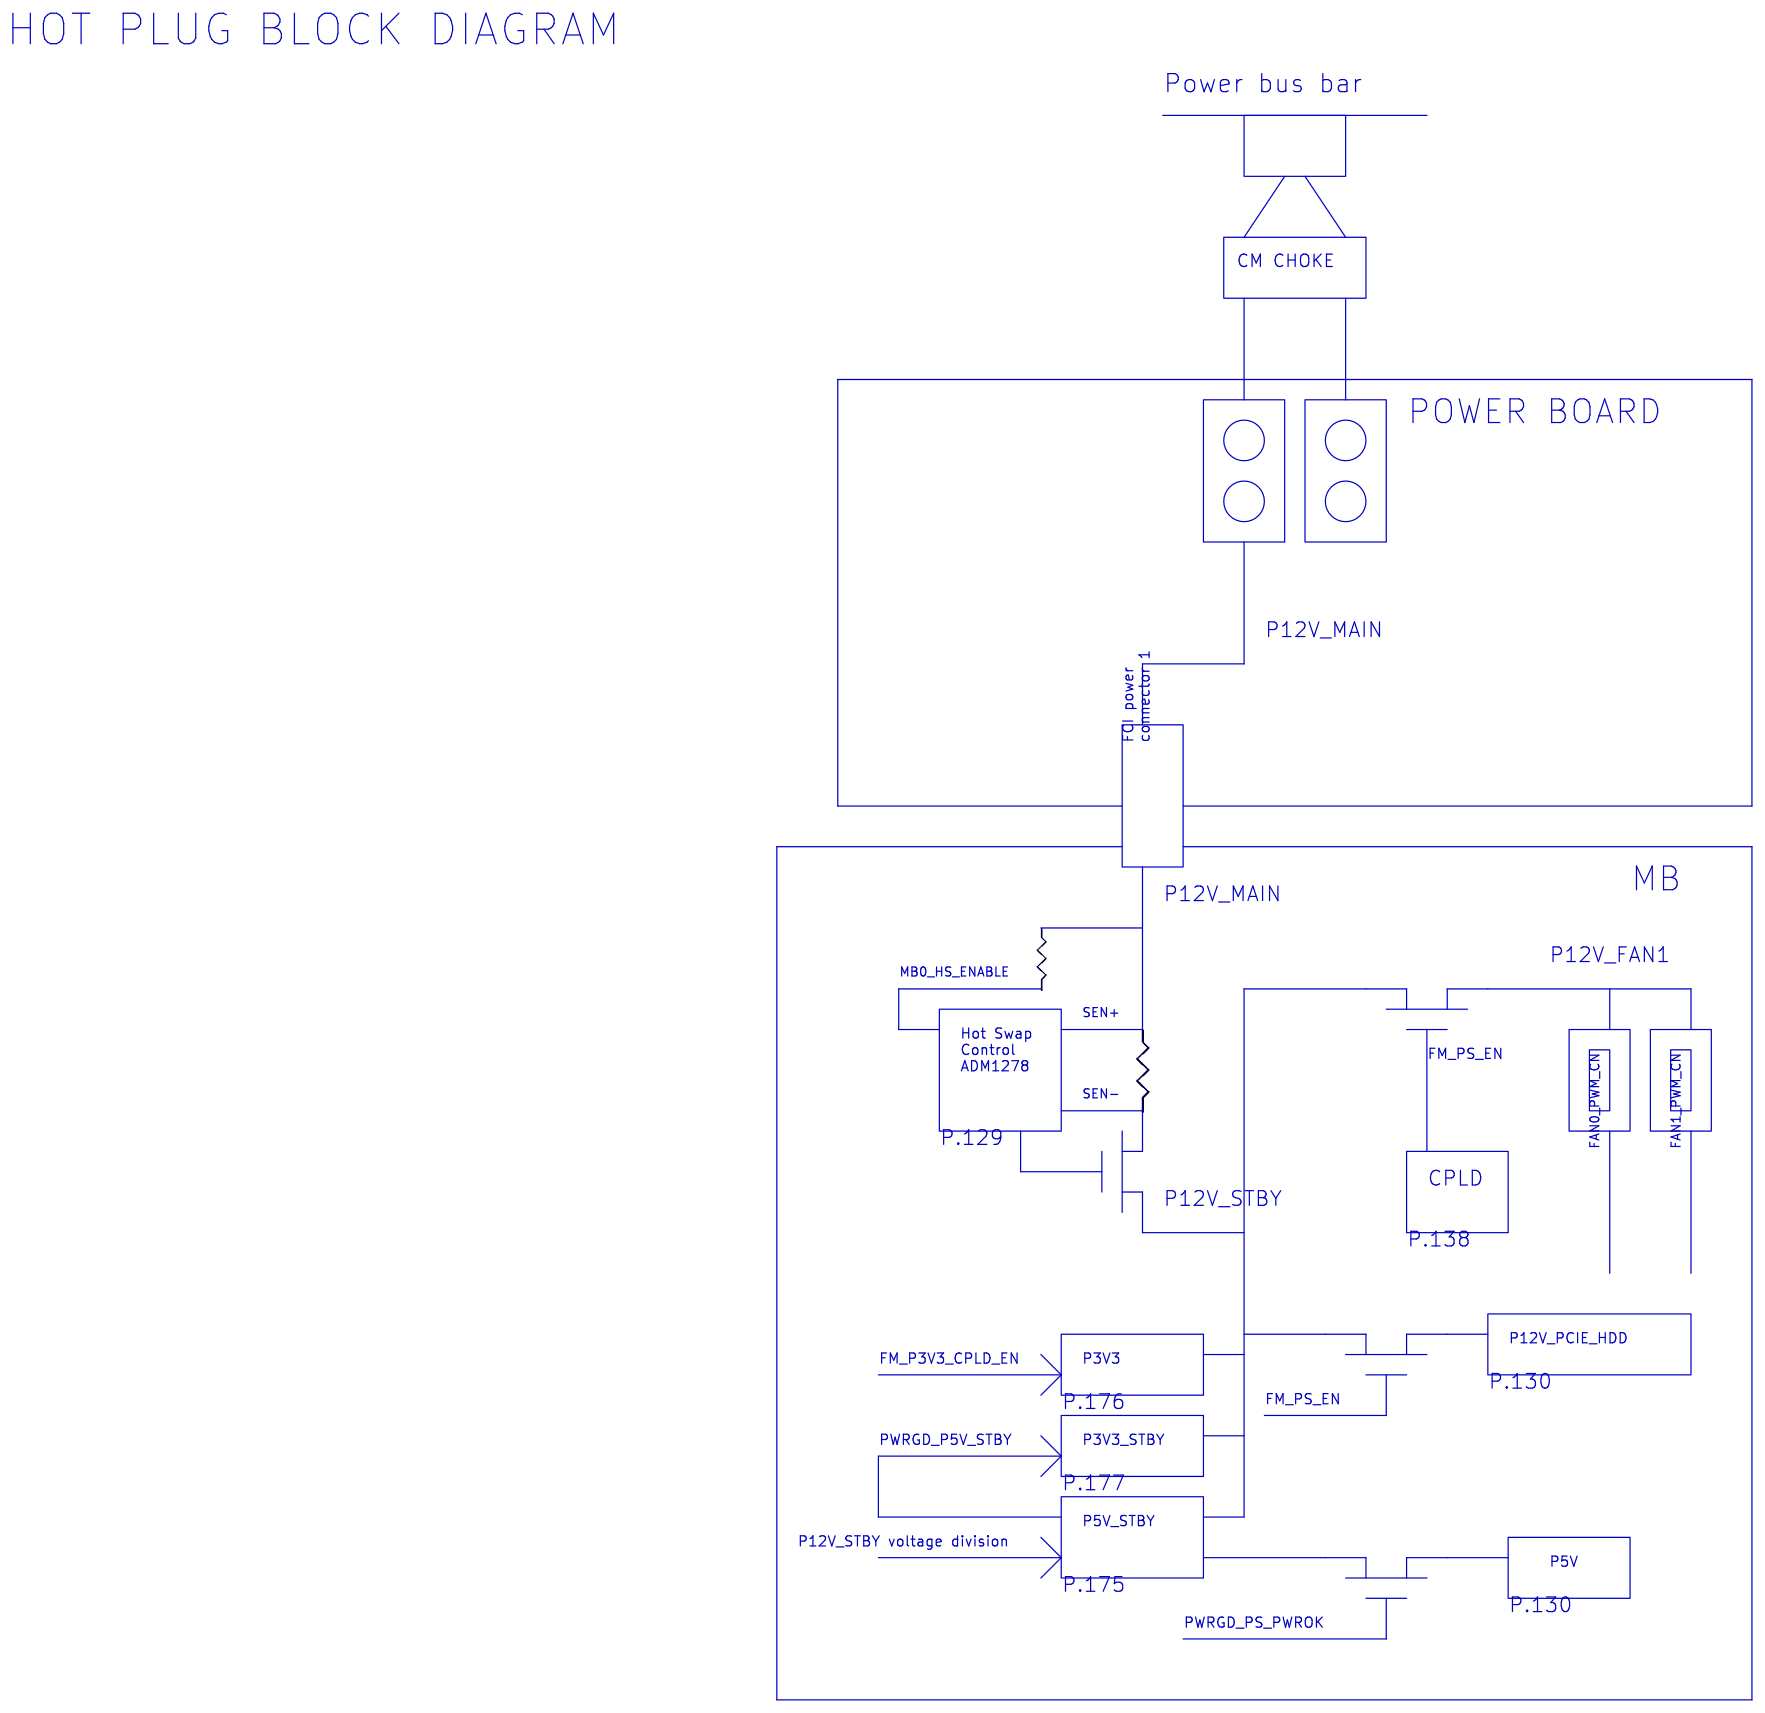
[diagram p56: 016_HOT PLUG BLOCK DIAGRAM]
148 015_RESISTOR DEFINITIONS: title: RESISTOR DEFINITIONS
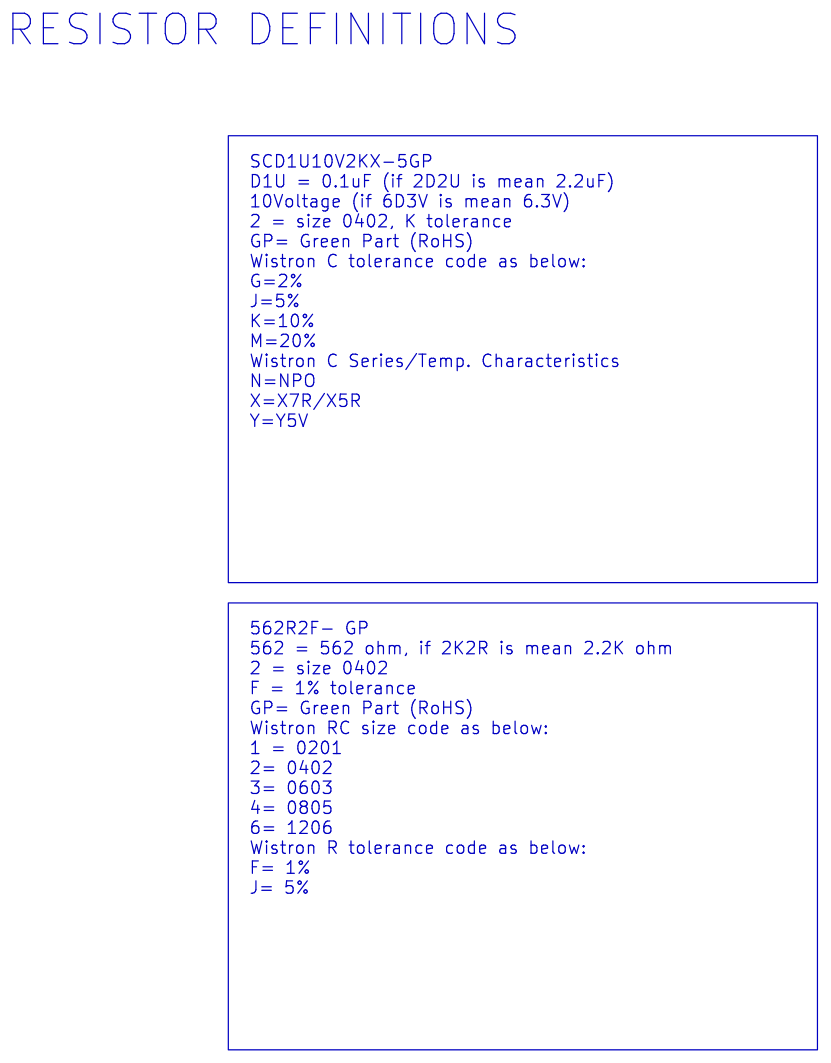
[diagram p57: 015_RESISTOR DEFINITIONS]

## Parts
sheet 024_CPU1 - MICS
C725  SCD01U25V2KX-3GP  [C402H22]
C861  SCD01U25V2KX-3GP  [C402H22]
R3  220R2F-GP  [R402H16]
R4  100R2F-L1-GP-U  [R402H14]
R5  100R2F-L1-GP-U  [R402H14]
R6  1KR2F-L-GP  [R402H16]
R7  1KR2F-L-GP  [R402H16]
R8  2R2J-2-GP  [R402H16]
R9  2R2J-2-GP  [R402H16]
R10  1KR2F-L-GP  [R402H16]
R11  1KR2F-L-GP  [R402H16]
R13  0R2J-2-GP  [R402H16]
R28  0R2J-2-GP  [R402H16]
R1137  0R2J-2-GP  [R402H16]
TP1  TP20B24R10-B-GP  [TP20B24R10-B]
TP2  TP20B24R10-B-GP  [TP20B24R10-B]
TP4  TP20B24R10-B-GP  [TP20B24R10-B]
TP5  TP20B24R10-B-GP  [TP20B24R10-B]
TP6  TP20B24R10-B-GP  [TP20B24R10-B]
TP7  TP20B24R10-B-GP  [TP20B24R10-B]
TP8  TP20B24R10-B-GP  [TP20B24R10-B]
TP9  TP20B24R10-B-GP  [TP20B24R10-B]
TP10  TP20B24R10-B-GP  [TP20B24R10-B]
TP11  TP20B24R10-B-GP  [TP20B24R10-B]
TP210  TP20B24R10-B-GP  [TP20B24R10-B]
TP211  TP20B24R10-B-GP  [TP20B24R10-B]
sheet 025_CPU1 - RESERVED PINS
R418  49D9R2F-GP  [R402H16]
R419  49D9R2F-GP  [R402H16]
R421  49D9R2F-GP  [R402H16]
R627  49D9R2F-GP  [R402H16]
TP13  TP20B24R10-B-GP  [TP20B24R10-B]
TP14  TP20B24R10-B-GP  [TP20B24R10-B]
TP15  TP20B24R10-B-GP  [TP20B24R10-B]
TP16  TP20B24R10-B-GP  [TP20B24R10-B]
TP17  TP20B24R10-B-GP  [TP20B24R10-B]
TP18  TP20B24R10-B-GP  [TP20B24R10-B]
TP19  TP20B24R10-B-GP  [TP20B24R10-B]
TP21  TP20B24R10-B-GP  [TP20B24R10-B]
TP22  TP20B24R10-B-GP  [TP20B24R10-B]
TP23  TP20B24R10-B-GP  [TP20B24R10-B]
TP24  TP20B24R10-B-GP  [TP20B24R10-B]
TP25  TP20B24R10-B-GP  [TP20B24R10-B]
TP26  TP20B24R10-B-GP  [TP20B24R10-B]
TP27  TP20B24R10-B-GP  [TP20B24R10-B]
TP28  TP20B24R10-B-GP  [TP20B24R10-B]
TP29  TP20B24R10-B-GP  [TP20B24R10-B]
TP30  TP20B24R10-B-GP  [TP20B24R10-B]
TP31  TP20B24R10-B-GP  [TP20B24R10-B]
TP32  TP20B24R10-B-GP  [TP20B24R10-B]
TP33  TP20B24R10-B-GP  [TP20B24R10-B]
TP34  TP20B24R10-B-GP  [TP20B24R10-B]
TP35  TP20B24R10-B-GP  [TP20B24R10-B]
TP36  TP20B24R10-B-GP  [TP20B24R10-B]
TP37  TP20B24R10-B-GP  [TP20B24R10-B]
TP38  TP20B24R10-B-GP  [TP20B24R10-B]
TP39  TP20B24R10-B-GP  [TP20B24R10-B]
TP40  TP20B24R10-B-GP  [TP20B24R10-B]
TP41  TP20B24R10-B-GP  [TP20B24R10-B]
TP42  TP20B24R10-B-GP  [TP20B24R10-B]
TP43  TP20B24R10-B-GP  [TP20B24R10-B]
TP44  TP20B24R10-B-GP  [TP20B24R10-B]
TP45  TP20B24R10-B-GP  [TP20B24R10-B]
TP47  TP20B24R10-B-GP  [TP20B24R10-B]
TP48  TP20B24R10-B-GP  [TP20B24R10-B]
TP49  TP20B24R10-B-GP  [TP20B24R10-B]
TP50  TP20B24R10-B-GP  [TP20B24R10-B]
TP51  TP20B24R10-B-GP  [TP20B24R10-B]
TP52  TP20B24R10-B-GP  [TP20B24R10-B]
TP53  TP20B24R10-B-GP  [TP20B24R10-B]
TP54  TP20B24R10-B-GP  [TP20B24R10-B]
TP55  TP20B24R10-B-GP  [TP20B24R10-B]
TP56  TP20B24R10-B-GP  [TP20B24R10-B]
TP57  TP20B24R10-B-GP  [TP20B24R10-B]
TP58  TP20B24R10-B-GP  [TP20B24R10-B]
TP59  TP20B24R10-B-GP  [TP20B24R10-B]
TP60  TP20B24R10-B-GP  [TP20B24R10-B]
TP61  TP20B24R10-B-GP  [TP20B24R10-B]
TP62  TP20B24R10-B-GP  [TP20B24R10-B]
TP64  TP20B24R10-B-GP  [TP20B24R10-B]
TP65  TP20B24R10-B-GP  [TP20B24R10-B]
TP66  TP20B24R10-B-GP  [TP20B24R10-B]
TP67  TP20B24R10-B-GP  [TP20B24R10-B]
TP68  TP20B24R10-B-GP  [TP20B24R10-B]
TP69  TP20B24R10-B-GP  [TP20B24R10-B]
TP70  TP20B24R10-B-GP  [TP20B24R10-B]
TP71  TP20B24R10-B-GP  [TP20B24R10-B]
TP72  TP20B24R10-B-GP  [TP20B24R10-B]
TP73  TP20B24R10-B-GP  [TP20B24R10-B]
TP74  TP20B24R10-B-GP  [TP20B24R10-B]
TP75  TP20B24R10-B-GP  [TP20B24R10-B]
TP76  TP20B24R10-B-GP  [TP20B24R10-B]
TP77  TP20B24R10-B-GP  [TP20B24R10-B]
TP78  TP20B24R10-B-GP  [TP20B24R10-B]
TP79  TP20B24R10-B-GP  [TP20B24R10-B]
TP80  TP20B24R10-B-GP  [TP20B24R10-B]
TP81  TP20B24R10-B-GP  [TP20B24R10-B]
TP82  TP20B24R10-B-GP  [TP20B24R10-B]
sheet 035_CPU1 - VCCIN & VDDQ
CPU1  HASWELL-EP  [SKT-LGA2011M6151-1H298]  (sections A,B,C,D,E,F,G,H,I,J,K,L,M,N,O,P,Q,R)

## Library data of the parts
C725 C861 = SCD01U25V2KX-3GP: CHIP 0.01U 25V K0402 X7R(ROHS); Category: CPU0; DESCRIPTIO: CHIP 0.01U 25V K0402 X7R(ROHS); GREENDFACTOR: R2_SA;HF_SA;G_SA;; Package Type: SMD-BCG; Part Number: 78.10322.2FL; Part Type: SMD-BCG; SPEC: http://wpqssvr.wistron.com.tw:7001/wpqs/servlet/COM.qpart.Attachment?PartNumber=78.10322.2FL; Type: SMD; VENDORPARTNUMBER: 04023C103KAT2A/C1005X7R103KFT/GRM155R71E103KA01D/223891715636/CL05B103KA5NNNC/TMK105BJ103KV-F/C1005X7R1E103KT000F; Vendor PN: 04023C103KAT2A/C1005X7R103KFT/GRM155R71E103KA01D/223891715636/CL05B103KA5NNNC/TMK105BJ103KV-F/C1005X7R1E103KT000F
R3 = 220R2F-GP: CHIP RES 220 F 1/16W 0402; Category: CPU0; GREENDFACTOR: R2_SA;HF_SA;G_SA;; Package Type: RCL_GP; Part Number: 64.22005.6DL; SPEC: http://wpqssvr.wistron.com.tw:7001/wpqs/servlet/COM.qpart.Attachment?PartNumber=64.22005.6DL
R4 R5 = 100R2F-L1-GP-U: CHIP RES 100 F 1/16W 0402; Category: CPU0; Part Number: 64.10005.6DL; Part Type: SMD-RG
R6 R7 R10 R11 = 1KR2F-L-GP: CHIP RES 1K F 1/16W 0402; Category: CPU0; Part Number: 64.10015.L1L; Part Type: SMD-RG2
R8 R9 = 2R2J-2-GP: CHIP RES 2 J 1/16W 0402; Category: CPU0; GREENDFACTOR: R2_SA;HF_SA;G_SA;; Package Type: SMD-RG1; Part Number: 63.2R034.1DL; SPEC: http://wpqssvr.wistron.com.tw:7001/wpqs/servlet/COM.qpart.Attachment?PartNumber=63.2R034.1DL
R13 R28 R1137 = 0R2J-2-GP: CHIP RES 0 J 1/16W 0402; Category: BMC; DESCRIPTIO: CHIP RES 0 J 1/16W 0402; GREENDFACTOR: R2_SA;HF_SA;G_SA;; Package Type: SMD-RG; Part Number: 63.R0034.1DL; Part Type: SMD-RG; SPEC: http://wpqssvr.wistron.com.tw:7001/wpqs/servlet/COM.qpart.Attachment?PartNumber=63.R0034.1DL; VENDORPARTNUMBER: RM04JTN0/RTT02000JTH/RR0510X-000-XN/RC0402JR-070RL/WR04X000 PTL
TP1 TP2 TP4-TP11 TP13-TP19 TP21-TP45 TP47-TP62 TP64-TP82 TP210 TP211 = TP20B24R10-B-GP_4: TEST VIA FOR DRILL 10MIL; GREENDFACTOR: R2_C;; Package Type: DISCRET-G5; Part Number: ZZ.0TPAD.211; SPEC: http://wpqssvr.wistron.com.tw:7001/wpqs/servlet/COM.qpart.Attachment?PartNumber=ZZ.0TPAD.211
R418 R419 R421 R627 = 49D9R2F-GP: CHIP RES 49.9 F 1/16W 0402; Category: CPU0; Part Number: 64.49R95.6DL; Part Type: RCL_GP
CPU1 = HASWELL-EP: SKT CPU LGA 2011P AZIF0001-P004C SMD; GREENDFACTOR: R2_C;; POP?: 62.10079.311; Package Type: SOCKET-G2; Part Number: 62.10079.261; SPEC: http://wpqssvr.wistron.com.tw:7001/wpqs/servlet/COM.qpart.Attachment?PartNumber=62.10079.261

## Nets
GND: C725.2 C861.2 CPU1.BA55(RSVD#BA55) R10.2 R11.2 R418.2 R419.2 R421.2 R627.2 ; also on sheet 1 2 3 4 5 6 7 8 9 10 11 12 13 14 15 16 17 18 19 20 21 22 23 24 25 26 27 28 29 30 31 32 33 34 35 36 37 38 39 44 46 47 49 50 51 52 53 54 55 56 57 58 59 60 61 62 63 64 65 66 69 70 71 73 74 75 76 78 79 80 81 82 83 84 86 87 88 89 90 91 92 93 94 95 96 97 98 99 100 101 102 103 104 105 106 107 108 109 110 111 112 113 114 115 116 117 118 119 128 129 159 160 161 166 168 169 170 171 172 173 174 175 176 177 180 181 182 183 184
PVCCIO: R4.1 R5.1 ; also on sheet 11 16 26 35 39 46 47 68 87 97 100 101 102 103 120 129 130 160 173 177 179 182
PVDDQ_AB: R6.1 ; also on sheet 28 30 45 52 97 116 117 118 119 130
PVDDQ_CD: R7.1 ; also on sheet 23 25 45 97 112 113 114 115 130
CLK_100M_CPU0_BCLK0_DN: CPU1.CN41(BCLK0_DN) ; also on sheet 56
CLK_100M_CPU0_BCLK0_DP: CPU1.CL41(BCLK0_DP) ; also on sheet 56
CLK_100M_CPU0_BCLK1_DN: CPU1.AW45(BCLK1_DN) ; also on sheet 56
CLK_100M_CPU0_BCLK1_DP: CPU1.BA45(BCLK1_DP) ; also on sheet 56
FM_CPU0_BDX_PRSNT_LVT3_N: CPU1.AB48(PROC_ID) ; also on sheet 11 51 179
FM_CPU0_SKTOCC_BMC_LVT3_N: R1137.2 ; also on sheet 180
FM_CPU0_SKTOCC_LVT3_N: CPU1.BU49(SKTOCC#) R1137.1 ; also on sheet 46 51 179
H_CPU0_CATERR_G_N: CPU1.CC51(CATERR#) ; also on sheet 100
H_CPU0_ERR0_G_N: CPU1.BD50(ERROR_N0) ; also on sheet 102
H_CPU0_ERR1_G_N: CPU1.BB48(ERROR_N1) ; also on sheet 102
H_CPU0_ERR2_G_N: CPU1.BB52(ERROR_N2) ; also on sheet 102
H_CPU0_FAST_WAKE_G_N: CPU1.AV44(PM_FAST_WAKE#) ; also on sheet 179
H_CPU0_FIVR_FAULT_G: CPU1.CY40(FIVR_FAULT) ; also on sheet 101 179
H_CPU0_MEMAB_MEMHOT_G_N: CPU1.CL33(MEM_HOT_C1#) ; also on sheet 101 181 183
H_CPU0_MEMCD_MEMHOT_G_N: CPU1.P36(MEM_HOT_C23#) ; also on sheet 101 181 183
H_CPU0_MSMI_G_N: CPU1.H52(MSMI#) ; also on sheet 179
H_CPU0_PROCHOT_G_N: CPU1.BL51(PROCHOT#) ; also on sheet 101 181 183
H_CPU0_THERMTRIP_G_N: CPU1.BJ47(THERMTRIP#) ; also on sheet 101 179
H_PM_SYNC_G: CPU1.K52(PMSYNC) ; also on sheet 91 129
M_A_ACT_N: CPU1.CK16(DDR0_ACT#) ; also on sheet 118 119
M_A_ALERT_N: CPU1.CD16(DDR0_ALERT#) ; also on sheet 118 119
M_A_BA_0: CPU1.CL21(DDR0_BA0) ; also on sheet 118 119
M_A_BA_1: CPU1.CH20(DDR0_BA1) ; also on sheet 118 119
M_A_BG_0: CPU1.CL17(DDR0_BG0) ; also on sheet 118 119
M_A_BG_1: CPU1.CN17(DDR0_BG1) ; also on sheet 118 119
M_A_C_2: CPU1.CJ25(DDR0_CID2) ; also on sheet 118 119
M_A_CKE_0: CPU1.CJ17(DDR0_CKE0) ; also on sheet 119
M_A_CKE_1: CPU1.CE17(DDR0_CKE1) ; also on sheet 119
M_A_CKE_2: CPU1.CF16(DDR0_CKE2) ; also on sheet 118
M_A_CKE_3: CPU1.CC17(DDR0_CKE3) ; also on sheet 118
M_A_CLK_DN_0: CPU1.CE21(DDR0_CLK_DN0) ; also on sheet 119
M_A_CLK_DN_1: CPU1.CF18(DDR0_CLK_DN1) ; also on sheet 118
M_A_CLK_DN_2: CPU1.CF20(DDR0_CLK_DN2) ; also on sheet 119
M_A_CLK_DN_3: CPU1.CE19(DDR0_CLK_DN3) ; also on sheet 118
M_A_CLK_DP_0: CPU1.CC21(DDR0_CLK_DP0) ; also on sheet 119
M_A_CLK_DP_1: CPU1.CD18(DDR0_CLK_DP1) ; also on sheet 118
M_A_CLK_DP_2: CPU1.CD20(DDR0_CLK_DP2) ; also on sheet 119
M_A_CLK_DP_3: CPU1.CC19(DDR0_CLK_DP3) ; also on sheet 118
M_A_CS_N_0: CPU1.CD22(DDR0_CS0#) ; also on sheet 119
M_A_CS_N_1: CPU1.CH22(DDR0_CS1#) ; also on sheet 119
M_A_CS_N_2: CPU1.CF26(DDR0_CS2#/CID0) ; also on sheet 119
M_A_CS_N_3: CPU1.CC25(DDR0_CS3#/CID1) ; also on sheet 119
M_A_CS_N_4: CPU1.CK22(DDR0_CS4#) ; also on sheet 118
M_A_CS_N_5: CPU1.CH24(DDR0_CS5#) ; also on sheet 118
M_A_CS_N_6: CPU1.CH26(DDR0_CS6#/CID3) ; also on sheet 118
M_A_CS_N_7: CPU1.CD26(DDR0_CS7#/CID4) ; also on sheet 118
M_A_DQ_0: CPU1.BU7(DDR0_DQ0) ; also on sheet 118 119
M_A_DQ_1: CPU1.BT6(DDR0_DQ1) ; also on sheet 118 119
M_A_DQ_2: CPU1.CA9(DDR0_DQ2) ; also on sheet 118 119
M_A_DQ_3: CPU1.CB8(DDR0_DQ3) ; also on sheet 118 119
M_A_DQ_4: CPU1.BT8(DDR0_DQ4) ; also on sheet 118 119
M_A_DQ_5: CPU1.BU9(DDR0_DQ5) ; also on sheet 118 119
M_A_DQ_6: CPU1.CA7(DDR0_DQ6) ; also on sheet 118 119
M_A_DQ_7: CPU1.CB6(DDR0_DQ7) ; also on sheet 118 119
M_A_DQ_8: CPU1.BT12(DDR0_DQ8) ; also on sheet 118 119
M_A_DQ_9: CPU1.BU11(DDR0_DQ9) ; also on sheet 118 119
M_A_DQ_10: CPU1.BW13(DDR0_DQ10) ; also on sheet 118 119
M_A_DQ_11: CPU1.BY14(DDR0_DQ11) ; also on sheet 118 119
M_A_DQ_12: CPU1.BT14(DDR0_DQ12) ; also on sheet 118 119
M_A_DQ_13: CPU1.BU15(DDR0_DQ13) ; also on sheet 118 119
M_A_DQ_14: CPU1.CA11(DDR0_DQ14) ; also on sheet 118 119
M_A_DQ_15: CPU1.BY12(DDR0_DQ15) ; also on sheet 118 119
M_A_DQ_16: CPU1.CE9(DDR0_DQ16) ; also on sheet 118 119
M_A_DQ_17: CPU1.CF8(DDR0_DQ17) ; also on sheet 118 119
M_A_DQ_18: CPU1.CK10(DDR0_DQ18) ; also on sheet 118 119
M_A_DQ_19: CPU1.CJ11(DDR0_DQ19) ; also on sheet 118 119
M_A_DQ_20: CPU1.CD10(DDR0_DQ20) ; also on sheet 118 119
M_A_DQ_21: CPU1.CE11(DDR0_DQ21) ; also on sheet 118 119
M_A_DQ_22: CPU1.CK8(DDR0_DQ22) ; also on sheet 118 119
M_A_DQ_23: CPU1.CJ9(DDR0_DQ23) ; also on sheet 118 119
M_A_DQ_24: CPU1.CE13(DDR0_DQ24) ; also on sheet 118 119
M_A_DQ_25: CPU1.CG15(DDR0_DQ25) ; also on sheet 118 119
M_A_DQ_26: CPU1.CM14(DDR0_DQ26) ; also on sheet 118 119
M_A_DQ_27: CPU1.CH14(DDR0_DQ27) ; also on sheet 118 119
M_A_DQ_28: CPU1.CC13(DDR0_DQ28) ; also on sheet 118 119
M_A_DQ_29: CPU1.CD14(DDR0_DQ29) ; also on sheet 118 119
M_A_DQ_30: CPU1.CM12(DDR0_DQ30) ; also on sheet 118 119
M_A_DQ_31: CPU1.CL13(DDR0_DQ31) ; also on sheet 118 119
M_A_DQ_32: CPU1.CK28(DDR0_DQ32) ; also on sheet 118 119
M_A_DQ_33: CPU1.CH28(DDR0_DQ33) ; also on sheet 118 119
M_A_DQ_34: CPU1.CK32(DDR0_DQ34) ; also on sheet 118 119
M_A_DQ_35: CPU1.CH32(DDR0_DQ35) ; also on sheet 118 119
M_A_DQ_36: CPU1.CL27(DDR0_DQ36) ; also on sheet 118 119
M_A_DQ_37: CPU1.CJ27(DDR0_DQ37) ; also on sheet 118 119
M_A_DQ_38: CPU1.CL31(DDR0_DQ38) ; also on sheet 118 119
M_A_DQ_39: CPU1.CJ31(DDR0_DQ39) ; also on sheet 118 119
M_A_DQ_40: CPU1.CD28(DDR0_DQ40) ; also on sheet 118 119
M_A_DQ_41: CPU1.CB28(DDR0_DQ41) ; also on sheet 118 119
M_A_DQ_42: CPU1.CD32(DDR0_DQ42) ; also on sheet 118 119
M_A_DQ_43: CPU1.CB32(DDR0_DQ43) ; also on sheet 118 119
M_A_DQ_44: CPU1.CE27(DDR0_DQ44) ; also on sheet 118 119
M_A_DQ_45: CPU1.CC27(DDR0_DQ45) ; also on sheet 118 119
M_A_DQ_46: CPU1.CE31(DDR0_DQ46) ; also on sheet 118 119
M_A_DQ_47: CPU1.CC31(DDR0_DQ47) ; also on sheet 118 119
M_A_DQ_48: CPU1.CE35(DDR0_DQ48) ; also on sheet 118 119
M_A_DQ_49: CPU1.CC35(DDR0_DQ49) ; also on sheet 118 119
M_A_DQ_50: CPU1.CE39(DDR0_DQ50) ; also on sheet 118 119
M_A_DQ_51: CPU1.CC39(DDR0_DQ51) ; also on sheet 118 119
M_A_DQ_52: CPU1.CF34(DDR0_DQ52) ; also on sheet 118 119
M_A_DQ_53: CPU1.CD34(DDR0_DQ53) ; also on sheet 118 119
M_A_DQ_54: CPU1.CF38(DDR0_DQ54) ; also on sheet 118 119
M_A_DQ_55: CPU1.CD38(DDR0_DQ55) ; also on sheet 118 119
M_A_DQ_56: CPU1.CL35(DDR0_DQ56) ; also on sheet 118 119
M_A_DQ_57: CPU1.CJ35(DDR0_DQ57) ; also on sheet 118 119
M_A_DQ_58: CPU1.CL39(DDR0_DQ58) ; also on sheet 118 119
M_A_DQ_59: CPU1.CJ39(DDR0_DQ59) ; also on sheet 118 119
M_A_DQ_60: CPU1.CM34(DDR0_DQ60) ; also on sheet 118 119
M_A_DQ_61: CPU1.CK34(DDR0_DQ61) ; also on sheet 118 119
M_A_DQ_62: CPU1.CM38(DDR0_DQ62) ; also on sheet 118 119
M_A_DQ_63: CPU1.CK38(DDR0_DQ63) ; also on sheet 118 119
M_A_DQS_DN_0: CPU1.BV6(DDR0_DQS_DN0) ; also on sheet 118 119
M_A_DQS_DN_1: CPU1.BW11(DDR0_DQS_DN1) ; also on sheet 118 119
M_A_DQS_DN_2: CPU1.CG11(DDR0_DQS_DN2) ; also on sheet 118 119
M_A_DQS_DN_3: CPU1.CJ13(DDR0_DQS_DN3) ; also on sheet 118 119
M_A_DQS_DN_4: CPU1.CM30(DDR0_DQS_DN4) ; also on sheet 118 119
M_A_DQS_DN_5: CPU1.CF30(DDR0_DQS_DN5) ; also on sheet 118 119
M_A_DQS_DN_6: CPU1.CE37(DDR0_DQS_DN6) ; also on sheet 118 119
M_A_DQS_DN_7: CPU1.CL37(DDR0_DQS_DN7) ; also on sheet 118 119
M_A_DQS_DN_8: CPU1.CT10(DDR0_DQS_DN8) ; also on sheet 118 119
M_A_DQS_DN_9: CPU1.BW9(DDR0_DQS_DN9) ; also on sheet 118 119
M_A_DQS_DN_10: CPU1.BV14(DDR0_DQS_DN10) ; also on sheet 118 119
M_A_DQS_DN_11: CPU1.CH8(DDR0_DQS_DN11) ; also on sheet 118 119
M_A_DQS_DN_12: CPU1.CF14(DDR0_DQS_DN12) ; also on sheet 118 119
M_A_DQS_DN_13: CPU1.CJ29(DDR0_DQS_DN13) ; also on sheet 118 119
M_A_DQS_DN_14: CPU1.CC29(DDR0_DQS_DN14) ; also on sheet 118 119
M_A_DQS_DN_15: CPU1.CD36(DDR0_DQS_DN15) ; also on sheet 118 119
M_A_DQS_DN_16: CPU1.CK36(DDR0_DQS_DN16) ; also on sheet 118 119
M_A_DQS_DN_17: CPU1.CW9(DDR0_DQS_DN17) ; also on sheet 118 119
M_A_DQS_DP_0: CPU1.BY6(DDR0_DQS_DP0) ; also on sheet 118 119
M_A_DQS_DP_1: CPU1.BV12(DDR0_DQS_DP1) ; also on sheet 118 119
M_A_DQS_DP_2: CPU1.CH10(DDR0_DQS_DP2) ; also on sheet 118 119
M_A_DQS_DP_3: CPU1.CK14(DDR0_DQS_DP3) ; also on sheet 118 119
M_A_DQS_DP_4: CPU1.CK30(DDR0_DQS_DP4) ; also on sheet 118 119
M_A_DQS_DP_5: CPU1.CD30(DDR0_DQS_DP5) ; also on sheet 118 119
M_A_DQS_DP_6: CPU1.CC37(DDR0_DQS_DP6) ; also on sheet 118 119
M_A_DQS_DP_7: CPU1.CJ37(DDR0_DQS_DP7) ; also on sheet 118 119
M_A_DQS_DP_8: CPU1.CV10(DDR0_DQS_DP8) ; also on sheet 118 119
M_A_DQS_DP_9: CPU1.BV8(DDR0_DQS_DP9) ; also on sheet 118 119
M_A_DQS_DP_10: CPU1.BU13(DDR0_DQS_DP10) ; also on sheet 118 119
M_A_DQS_DP_11: CPU1.CG9(DDR0_DQS_DP11) ; also on sheet 118 119
M_A_DQS_DP_12: CPU1.CG13(DDR0_DQS_DP12) ; also on sheet 118 119
M_A_DQS_DP_13: CPU1.CL29(DDR0_DQS_DP13) ; also on sheet 118 119
M_A_DQS_DP_14: CPU1.CE29(DDR0_DQS_DP14) ; also on sheet 118 119
M_A_DQS_DP_15: CPU1.CF36(DDR0_DQS_DP15) ; also on sheet 118 119
M_A_DQS_DP_16: CPU1.CM36(DDR0_DQS_DP16) ; also on sheet 118 119
M_A_DQS_DP_17: CPU1.CU9(DDR0_DQS_DP17) ; also on sheet 118 119
M_A_ECC_0: CPU1.CT8(DDR0_ECC0) ; also on sheet 118 119
M_A_ECC_1: CPU1.CV8(DDR0_ECC1) ; also on sheet 118 119
M_A_ECC_2: CPU1.CW11(DDR0_ECC2) ; also on sheet 118 119
M_A_ECC_3: CPU1.CU11(DDR0_ECC3) ; also on sheet 118 119
M_A_ECC_4: CPU1.CP8(DDR0_ECC4) ; also on sheet 118 119
M_A_ECC_5: CPU1.CN9(DDR0_ECC5) ; also on sheet 118 119
M_A_ECC_6: CPU1.CP10(DDR0_ECC6) ; also on sheet 118 119
M_A_ECC_7: CPU1.CR11(DDR0_ECC7) ; also on sheet 118 119
M_A_MA_0: CPU1.CP22(DDR0_MA0) ; also on sheet 118 119
M_A_MA_1: CPU1.CR21(DDR0_MA1) ; also on sheet 118 119
M_A_MA_2: CPU1.CT22(DDR0_MA2) ; also on sheet 118 119
M_A_MA_3: CPU1.CN21(DDR0_MA3) ; also on sheet 118 119
M_A_MA_4: CPU1.CP20(DDR0_MA4) ; also on sheet 118 119
M_A_MA_5: CPU1.CL19(DDR0_MA5) ; also on sheet 118 119
M_A_MA_6: CPU1.CN19(DDR0_MA6) ; also on sheet 118 119
M_A_MA_7: CPU1.CH18(DDR0_MA7) ; also on sheet 118 119
M_A_MA_8: CPU1.CJ19(DDR0_MA8) ; also on sheet 118 119
M_A_MA_9: CPU1.CK18(DDR0_MA9) ; also on sheet 118 119
M_A_MA_10: CPU1.CP24(DDR0_MA10) ; also on sheet 118 119
M_A_MA_11: CPU1.CP18(DDR0_MA11) ; also on sheet 118 119
M_A_MA_12: CPU1.CR17(DDR0_MA12) ; also on sheet 118 119
M_A_MA_13: CPU1.CE23(DDR0_MA13) ; also on sheet 118 119
M_A_MA_14: CPU1.CJ21(DDR0_MA14) ; also on sheet 118 119
M_A_MA_15: CPU1.CL25(DDR0_MA15) ; also on sheet 118 119
M_A_MA_16: CPU1.CL23(DDR0_MA16) ; also on sheet 118 119
M_A_MA_17: CPU1.CD24(DDR0_MA17) ; also on sheet 118 119
M_A_ODT_0: CPU1.CF22(DDR0_ODT0) ; also on sheet 119
M_A_ODT_1: CPU1.CN25(DDR0_ODT1) ; also on sheet 119
M_A_ODT_2: CPU1.CJ23(DDR0_ODT2) ; also on sheet 118
M_A_ODT_3: CPU1.CC23(DDR0_ODT3) ; also on sheet 118
M_A_PAR: CPU1.CK20(DDR0_PAR) ; also on sheet 118 119
M_AB_CPU_VREF: C725.1 CPU1.BY16(DDR1_VREF) R8.1
M_AB_RESET_N: CPU1.DC15(DDR_RESET_C1#) ; also on sheet 116 117 118 119
M_AB_VREF: R6.2 R8.2 R10.1 ; also on sheet 116 117 118 119
M_CD_CPU_VREF: C861.1 CPU1.T40(DDR23_VREF) R9.1
M_CD_RESET_N: CPU1.C23(DDR_RESET_C23#) ; also on sheet 112 113 114 115
M_CD_VREF: R7.2 R9.2 R11.1 ; also on sheet 112 113 114 115
PD_CPU0_BIST_ENABLE: CPU1.AJ43(BIST_ENABLE) ; also on sheet 103
PD_CPU0_TXT_PLTEN: CPU1.AF52(TXT_PLTEN) ; also on sheet 103
PECI_CPU_G: CPU1.CG55(PECI) ; also on sheet 68 129
PU_CPU0_BMCINIT: CPU1.AM48(BMCINIT) ; also on sheet 103
PU_CPU0_EAR_G_N: CPU1.CE53(EAR#) ; also on sheet 179
PU_CPU0_FRMAGENT: CPU1.Y48(FRMAGENT) ; also on sheet 103
PU_CPU0_SAFE_MODE_BOOT: CPU1.BK56(SAFE_MODE_BOOT) ; also on sheet 103
PU_CPU0_SOCKET_ID_0: CPU1.CP52(SOCKET_ID0) ; also on sheet 103
PU_CPU0_SOCKET_ID_1: CPU1.CC53(SOCKET_ID1) ; also on sheet 103
PU_CPU0_TXT_AGENT: CPU1.AH52(TXT_AGENT) ; also on sheet 103
PWRGD_CPU0_AB_DRAM_G: CPU1.CH16(DRAM_PWR_OK_C1) ; also on sheet 97
PWRGD_CPU0_CD_DRAM_G: CPU1.W29(DRAM_PWR_OK_C23) ; also on sheet 97
PWRGD_CPU0_G: CPU1.BJ53(PWRGOOD) ; also on sheet 47 97
RST_CPU0_G_N: CPU1.CR43(RESET#) ; also on sheet 47 97
SMB_DDR_AB_SCL_G: CPU1.CK42(DDR_SCL_C1) ; also on sheet 160
SMB_DDR_AB_SDA_G: CPU1.CM42(DDR_SDA_C1) ; also on sheet 160
SMB_DDR_CD_SCL_G: CPU1.V40(DDR_SCL_C23) ; also on sheet 160
SMB_DDR_CD_SDA_G: CPU1.Y40(DDR_SDA_C23) ; also on sheet 160
SRP_CPU_PWR_DEBUG_N: CPU1.AC41(PWR_DEBUG#) ; also on sheet 47 128
SVID_ALERT_CPU0_N: R3.2 ; also on sheet 26 31 39
SVID_ALERT_CPU0_R1_G: CPU1.AN43(SVIDALERT#) R3.1
SVID_CLK_CPU0: R28.2 ; also on sheet 26 31 39
SVID_CLK_CPU0_R: CPU1.AU43(SVIDCLK) R28.1
SVID_DIO_CPU0: R13.2 ; also on sheet 26 31 39
SVID_DIO_CPU0_R: CPU1.AR43(SVIDDATA) R13.1
TP_CPU0_PE_HP_SCL: CPU1.B46(PE_HP_SCL) TP210.1
TP_CPU0_PE_HP_SDA: CPU1.D46(PE_HP_SDA) TP211.1
TP_CPU0_RSVD_1: CPU1.DC3(RSVD#DC3) TP82.1
TP_CPU0_RSVD_2: CPU1.CY56(RSVD#CY56) TP80.1
TP_CPU0_RSVD_3: CPU1.R53(RSVD#R53) TP78.1
TP_CPU0_RSVD_4: CPU1.U53(RSVD#U53) TP76.1
TP_CPU0_RSVD_5: CPU1.CT50(RSVD#CT50) TP74.1
TP_CPU0_RSVD_6: CPU1.DA11(RSVD#DA11) TP72.1
TP_CPU0_RSVD_7: CPU1.BL47(RSVD#BL47) TP70.1
TP_CPU0_RSVD_8: CPU1.CA53(RSVD#CA53) TP68.1
TP_CPU0_RSVD_9: CPU1.AM54(RSVD#AM54) TP66.1
TP_CPU0_RSVD_10: CPU1.AP48(RSVD#AP48) TP64.1
TP_CPU0_RSVD_11: CPU1.AE45(RSVD#AE45) TP62.1
TP_CPU0_RSVD_12: CPU1.AA41(RSVD#AA41) TP60.1
TP_CPU0_RSVD_13: CPU1.Y54(RSVD#Y54) TP58.1
TP_CPU0_RSVD_14: CPU1.W41(RSVD#W41) TP81.1
TP_CPU0_RSVD_15: CPU1.V42(RSVD#V42) TP79.1
TP_CPU0_RSVD_16: CPU1.R43(RSVD#R43) TP77.1
TP_CPU0_RSVD_17: CPU1.P42(RSVD#P42) TP75.1
TP_CPU0_RSVD_18: CPU1.J41(RSVD#J41) TP73.1
TP_CPU0_RSVD_19: CPU1.H56(RSVD#H56) TP71.1
TP_CPU0_RSVD_20: CPU1.G43(RSVD#G43) TP69.1
TP_CPU0_RSVD_21: CPU1.F46(RSVD#F46) TP67.1
TP_CPU0_RSVD_22: CPU1.E53(RSVD#E53) TP65.1
TP_CPU0_RSVD_24: CPU1.C41(RSVD#C41) TP61.1
TP_CPU0_RSVD_25: CPU1.BH48(RSVD#BH48) TP59.1
TP_CPU0_RSVD_26: CPU1.AM44(RSVD#AM44) TP57.1
TP_CPU0_RSVD_27: CPU1.CF40(RSVD#CF40) TP2.1
TP_CPU0_RSVD_28: CPU1.CP40(RSVD#CP40) TP1.1
TP_CPU0_RSVD_29: CPU1.R41(RSVD#R41) TP5.1
TP_CPU0_RSVD_30: CPU1.M40(RSVD#M40) TP4.1
TP_CPU0_RSVD_33: CPU1.N41(RSVD#N41) TP42.1
TP_CPU0_RSVD_34: CPU1.CU51(RSVD#CU51) TP40.1
TP_CPU0_RSVD_35: CPU1.CW51(RSVD#CW51) TP38.1
TP_CPU0_RSVD_36: CPU1.B54(RSVD#B54) TP36.1
TP_CPU0_RSVD_37: CPU1.DB56(RSVD#DB56) TP54.1
TP_CPU0_RSVD_38: CPU1.A53(RSVD#A53) TP52.1
TP_CPU0_RSVD_39: CPU1.F58(RSVD#F58) TP50.1
TP_CPU0_RSVD_40: CPU1.E57(RSVD#E57) TP48.1
TP_CPU0_RSVD_41: CPU1.AL55(RSVD#AL55) TP56.1
TP_CPU0_RSVD_42: CPU1.BD48(RSVD#BD48) TP11.1
TP_CPU0_RSVD_43: CPU1.AJ55(RSVD#AJ55) TP10.1
TP_CPU0_RSVD_44: CPU1.AY46(RSVD#AY46) TP9.1
TP_CPU0_RSVD_45: CPU1.AV46(RSVD#AV46) TP8.1
TP_CPU0_RSVD_46: CPU1.CR51(RSVD#CR51) TP7.1
TP_CPU0_RSVD_48: CPU1.BT44(RSVD#BT44) TP55.1
TP_CPU0_RSVD_49: CPU1.CA43(RSVD#CA43) TP53.1
TP_CPU0_RSVD_50: CPU1.BV44(RSVD#BV44) TP51.1
TP_CPU0_RSVD_51: CPU1.BY44(RSVD#BY44) TP49.1
TP_CPU0_RSVD_52: CPU1.BK44(RSVD#BK44) TP47.1
TP_CPU0_RSVD_53: CPU1.BN45(RSVD#BN45) TP45.1
TP_CPU0_RSVD_54: CPU1.BM44(RSVD#BM44) TP44.1
TP_CPU0_RSVD_55: CPU1.BR45(RSVD#BR45) TP43.1
TP_CPU0_RSVD_56: CPU1.BL43(RSVD#BL43) TP41.1
TP_CPU0_RSVD_57: CPU1.BP44(RSVD#BP44) TP39.1
TP_CPU0_RSVD_58: CPU1.BU43(RSVD#BU43) TP37.1
TP_CPU0_RSVD_59: CPU1.BR43(RSVD#BR43) TP35.1
TP_CPU0_RSVD_60: CPU1.BD44(RSVD#BD44) TP34.1
TP_CPU0_RSVD_61: CPU1.BF44(RSVD#BF44) TP33.1
TP_CPU0_RSVD_62: CPU1.BH46(RSVD#BH46) TP32.1
TP_CPU0_RSVD_63: CPU1.BG43(RSVD#BG43) TP30.1
TP_CPU0_RSVD_64: CPU1.BE43(RSVD#BE43) TP28.1
TP_CPU0_RSVD_65: CPU1.BJ45(RSVD#BJ45) TP18.1
TP_CPU0_RSVD_66: CPU1.BH44(RSVD#BH44) TP27.1
TP_CPU0_RSVD_67: CPU1.BJ43(RSVD#BJ43) TP17.1
TP_CPU0_RSVD_68: CPU1.DE53(RSVD#DE53) TP16.1
TP_CPU0_RSVD_69: CPU1.C53(RSVD#C53) TP6.1
TP_CPU0_RSVD_70: CPU1.F56(RSVD#F56) TP26.1
TP_CPU0_RSVD_71: CPU1.D56(RSVD#D56) TP14.1
TP_CPU0_RSVD_72: CPU1.K58(RSVD#K58) TP23.1
TP_CPU0_RSVD_73: CPU1.H58(RSVD#H58) TP13.1
TP_CPU0_RSVD_76: CPU1.DE55(RSVD#DE55) TP15.1
TP_CPU0_RSVD_77: CPU1.DD54(RSVD#DD54) TP25.1
TP_CPU0_RSVD_78: CPU1.CY58(RSVD#CY58) TP24.1
TP_CPU0_RSVD_79: CPU1.DA57(RSVD#DA57) TP22.1
TP_CPU0_RSVD_80: CPU1.BP46(RSVD#BP46) TP21.1
TP_CPU0_RSVD_81: CPU1.BM46(RSVD#BM46) TP19.1
TP_CPU0_RSVD_82: CPU1.CN43(RSVD#CN43) TP29.1
TP_CPU0_RSVD_83: CPU1.CL43(RSVD#CL43) TP31.1
TP_CPU0_TEST_0: CPU1.DB2(TEST0) R627.1
TP_CPU0_TEST_1: CPU1.DB4(TEST1) R418.1
TP_CPU0_TEST_2: CPU1.D2(TEST2) R419.1
TP_CPU0_TEST_3: CPU1.C3(TEST3) R421.1
XDP_CPU0_OBSDATA_A_MBP2_G_N: CPU1.BE47(BPM_N2) ; also on sheet 47
XDP_CPU0_OBSDATA_A_MBP3_G_N: CPU1.BF46(BPM_N3) ; also on sheet 47
XDP_CPU0_OBSDATA_A_MBP4_G_N: CPU1.BE45(BPM_N4) ; also on sheet 47
XDP_CPU0_OBSDATA_A_MBP5_G_N: CPU1.BD46(BPM_N5) ; also on sheet 47
XDP_CPU0_PRDY_G_N: CPU1.CU49(PRDY#) ; also on sheet 46 47
XDP_CPU0_PREQ_G_N: CPU1.CW49(PREQ#) ; also on sheet 46 47
XDP_CPU0_TDI_G: CPU1.CF42(TDI) ; also on sheet 46
XDP_CPU0_TDO_G: CPU1.CG41(TDO) ; also on sheet 46
XDP_CPU_MBP0_G_N: CPU1.BC43(BPM_N0) R5.2 ; also on sheet 129
XDP_CPU_MBP1_G_N: CPU1.BB44(BPM_N1) R4.2 ; also on sheet 129
XDP_CPU_OBSFN_B_MBP6_G_N: CPU1.BA43(BPM_N6) ; also on sheet 47 129
XDP_CPU_OBSFN_B_MBP7_G_N: CPU1.AW43(BPM_N7) ; also on sheet 47 129
XDP_CPU_TCK_G: CPU1.CA45(TCK) ; also on sheet 46 47 129
XDP_CPU_TMS_G: CPU1.BY46(TMS) ; also on sheet 46 47 129
XDP_CPU_TRST_G_N: CPU1.CV50(TRST#) ; also on sheet 46 47 129
XDP_PRESENT_N: CPU1.F40(DEBUG_EN#) ; also on sheet 47 128

Not connected (* = marked no-connect by the designer): CPU1 AR55(RSVD#AR55)* AU55(RSVD#AU55)* BF48(RSVD#BF48)* CC15(DDR0_CKE5)* CE25(DDR0_ODT5)* CF24(DDR0_ODT4)* CK24(DDR0_CS8#)* CK26(DDR0_CS9#)* CN15(DDR0_CKE4)*

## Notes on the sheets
sheet 137
- CPU1 - DDR4 (CHANNEL A)
- RAS_N/MA[16]
- CAS_N/MA[15]
- WE_N/MA[14]
- FAB1 REV003 20150318
- Chip ID : Used to select a single die out of the stack
- of a 3DS device.
- CID[4:3] are MUXed with CS_N[7:6], respectively.
- CID[1:0] are MUXed with CS_N[3:2], respectively.
- Activate. When asserted, indicated MA[16:14] are command signals.
sheet 138
- CPU1 - RESERVED PINS
sheet 139
- All processors must receive
  inactive to active transitions of PWRGOOD signal within 10 ns of each other.
- CPU1 - MICS
- All clocks to all Intel QPI agents (processors) should
  be routed on the same physical layer and must be
  matched within 0.5 inches.
- FROM CLK BUFFER
- FROM CLK BUFFER
- FAB1 REV005 20150323
- PLACE NEAR CPU0
- SVID PDG P.250
- FAB1 REV024 20150429
- ¡E Resistor values tolerance must not exceed 5%.
  ¡E Trace length matching must be used between the Clock and Data lines to ensure a
  length difference of no more than 250 mils.
  ¡E Data line should be routed between Alert and Clock lines.
  ¡E Good high-speed design practices must be used, such as avoiding routing over
  voids. If split crossing can¡¦t be avoided, place a decoupling capacitor between the
  two planes, within 0.150 in. of the SVID lines at each split crossing (0.1 £gF is
  recommended).
  ¡E SVID must be ground reference. Do not route SVID bus signals under phase nodes
  or high side MOSFET nodes that generate electrical noise.
  ¡E Routing impedance of the 3 lines should ensure nominal 50 ohm impedance.
  ¡E Low inductance path for VIO termination voltage to termination resistors (10 mils
  is the minimum trace width allowed). Bypass termination voltage as close as
  possible to termination resistor with 10 £gF and 0.1 £gF capacitors to ground
  (bypass is required unless supplied from a full plane).
  ¡E Microstrip (MS) and Stripline (SL) routing is allowed. Spacing of 12 mil on MS and
  13.5 mil on SL within the Clock and Data, and 15 mil to all other nonstatic lines.
  For 10 mil of spacing on SL, do not exceed this spacing for more than 2.5 inches.
  An exception is for the breakout regions, spacing between lines can drop to mil for
  coupling lengths less than 0.5 inches.
- Remove components
sheet 140
- NVDIMM Block Diagram
- P.128
- P.129
- CPLD2
- POWER_FAIL_1
- UV
  Monitor
- UV
- HSC
- P3V3
- P3V3_STBY
- P.137
- ADM1278
- 10.5V
- NVDIMM_UV_ALERT
- FM_ADR_TRIGGER_PF
- BMC
- P.82 - 93
- GPION5
- P.25- 37
- PCH
- FM_ADR_TRIGGER_EN
- CPU0
- H_PM_SYNC_G
- GPIOA2
- GPIO37
- POWER_FAIL
- FM_ADR_TRIGGER_N
- FM_ADR_BMC_TRIGGER
- GPIOA1
- (ADR_TRIGGER_N)
- PM_SYNC
- P.38 - 61
- CPU1
- H_PM_SYNC_G
- SYS_PWRBTN_N
- GPIOQ4
- PWRBTN
- PWRBTN#
- FM_BMC_PWRBTN_OUT_N
- GPIOQ5
- FM_ADR_COMPLETE
- RESERVED#D46
- GPIOG5
- P.108 - 110
- PR9B
- CPLD1
- SYS_PWROK
- PWRGD_SYS_PWROK
- PL5C
- RST_PLTRST_N
- PLTRST#
- PB3C
- SLP_S3#
- FM_BMC_ONCTL_N
- PT3C
- PT5B
- FM_ADR_COMPLETE_CPLD_SAVE
- Q50
- FM_ADR_COMPLETE_SAVE_N
- NVDIMMs
- P.138
- P.137
sheet 141
- JTAG BLOCK DIAGRAM
- P3V3_STBY
- CPLD
- CN51
- PLD
- CPLD1
- CPLD2
- JTAG_PLD_TDO
- JTAG_PLD1_TDO
- System
  CPLD
- TDO
- TDO
- Other
  PLD
- TDI
- JTAG_PLD_TDI
- JTAG_PLD1_TDI
- TDI
- JTAG_PLD_TMS
- JTAG_PLD1_TMS
- TMS
- TMS
- TCK
- JTAG_PLD_TCK
- JTAG_PLD1_TCK
- TCK
- P.138
- P.139
- P.137
- R554
  4.75k£[
- R669
  4.75k£[
- P3V3_STBY
- P3V3_STBY
- BMC1B
- From BMC
- U81
- BMC
- R1119
- NOPOP
- 1k£[
- VCC
- R1040
- 10k£[
- ARM_TDO
- R1111
- 0£[
- BMC_TDO
- 1A
- S
- BMC_JTAG_SELECT
- GPIOE5
- BMC UART
- ARM_TDI
- BMC_TDI
- 1B1
- JTAG_PLD_TDO
- R1112
- 0£[
- 2A
- P.108 - 110
- 1B2
- JTAG_PLD1_TDO
- ARM_TMS
- R1093
- 0£[
- BMC_TMS
- 3A
- 2B1
- JTAG_PLD_TDI
- ARM_TCK
- R1110
- 0£[
- BMC_TCK
- JTAG_PLD1_TDI
- 4A
- 2B2
- 3B1
- JTAG_PLD_TMS
- R684
- 220£[
- U81_EN_N
- OE#
- JTAG_PLD1_TMS
- 3B2
- 4B1
- JTAG_PLD_TCK
- JTAG_PLD1_TCK
- P.82 - 93
- 4B2
- To CPLD and PLD
- To PLD
- From PCH
- PCH
- GND
- P3V3_STBY
- P.139
- JTAG_PLD1_TMS
- PU_PCH_GP73_PLD_TMS
- R1035
- 475£[
- GPIO73
- JTAG_PLD1_TDI
- R1037
- 475£[
- SUS_STAT_N_PLD_TDI
- GPIO61
- BMC1C
- R934
  47k£[
- R927
  47k£[
- R930
  47k£[
- R915
  47k£[
- R911
  47k£[
- R910
  10k£[
- BMC
- JTAG_PLD1_TDO
- R1034
- 475£[
- JTAG_WBG_PLD_TDO
- ARM_NTRST
- NTRST
- GPIO26
- JTAG_PLD1_TCK
- JTAG_PCH_TCK
- ARM_TDI
- R1088
- 0£[
- GPIO56
- TDI_BDM
- R857
- PCH_GP56_PLD_TCK
- ARM_TMS
- TMS
- 0£[
- P3V3_STBY
- JTAG
- CN47
- ARM_TCK
- JTAG_WBG_PLD_TDO
- TCK
- R918
  10k£[
- FM_LA_TRIGGER_N_PLD_TDO
- ARM_RTCK
- RTCK
- ARM_TDO
- TDO
- BMC_RESET_N
- SRST#
- MISC
- NOPOP
- R931
  47k£[
- R913
  10k£[
- NOPOP
- R926
  0£[
- P.108 - 110
sheet 142
- P5V
- max = 12.5(V)
- Rsense
- P3V3_STBY
- P12V_MAIN
- P12V_MAIN
- P.130
- PVPP_AB(2V5)
- P12V_HDD_FAN1
- POWER CONN
- ADM1278
- In:P12V_STBY
- Out:
- 49k9£[
- 10k£[
- bus
  bar
- P12V_HDD_FAN1
- FAN_PWR_PG
- P3V3_STBY
- In:P12V_STBY
- Out:
- PWRCN2
- min = 12.47(V)
- VIH=1.1V
- U2
- U18
- TPS53318 x4
- PVPP_AB_PWRGD
- P.136
- P12V_STBY
- VIL=0.8V
- P.129
- 4.6(A) x 2.9(m£[) = 13.34(mV)
  12.5(V) - 16.24(mV) = 12.487(mV)
- VIH=2.4V
- VIL=0.4V
- EN
- PU18
- PGOOD
- P12V_PCIE_HDD
- P5V
- VIH=1.8V
- (OD)
- VIL=0.6V
- In:P12V_STBY
- Out:
- 49k9£[
- In:P5V_STBY
- Out:
- P.152
- P3V3_STBY
- P12V_PCIE_HDD
- PWRGD_PS_PWROK
- MOSFET
- VIH=2.4V
- VIL=0.4V
- U47
- Q22
- PWRGD_P5V
- CPLD1
- PVDDQ_AB
- Imin = 41.4(A)
  RDSon = 0.75(m£[)//0.75(m£[) = 0.375(m£[)
  Rsense = 0.0005(£[)//0.0005(£[) = 0.25(m£[)
  Vdrop = 41.4(A)*(0.375+0.25)(m£[) = 25.875(mV)
  12.5(V) - 25.875(mV) = 12.474(V)
- Imax = 48.8(A)
  RDSon = 0.75(m£[)//0.75(m£[) = 0.375(m£[)
  Rsense = 0.0005(£[)//0.0005(£[) = 0.25(m£[)
  Vdrop = 41.4(A)*(0.375+0.25)(m£[) = 30.5(mV)
  12.5(V) - 25.875(mV) = 12.47(V) ¡÷min
- 9(A) x 2.9(m£[) = 26.10(mV)
  12.5(V) - 26.1(mV) = 12.474(mV)
- P.130
- P.138
- In:P12V_STBY
- Out:
- 1k£[
- VRG5
- PX3244HDM x4
- PWRGD_PVPP_PVDDQ_AB
- FM_PS_EN
- P1V05_STBY_PCH
- EN
- PGOOD
- P5V_STBY
- VIH=0.8V
- PU13
- (OD)
- VIL=0.4V
- In:P12V_STBY
- Out:
- 6k65£[
- P.148
- In:P12V_STBY
- Out:
- TPS53511
- P3V3_STBY
- TPS53319
- PWRGD_P5V_STBY
- EN
- PGOOD
- PWRGD_P1V05_STBY_PCH_P1V0_STBY
- PVPP_CD(2V5)
- EN
- PGOOD
- CPLD1
- VIH=2V
- PU39
- (OD)
- (3V)
- VIH=1.8V
- PU52
- (OD)
- 10k£[
- VIL=0.4V
- VIL=0.6V
- P.170
- 10k£[
- In:P12V_STBY
- Out:
- 10k£[
- P.175
- FAB1 REV004 20150320
- TPS53318 x4
- FM_SLPS3_N
- FM_SLPA_N
- FM_VCC_MAIN_EN
- EN
- PGOOD
- PVPP_CD_PWRGD
- PU24
- (OD)
- P3V3_STBY
- 15k£[
- PVCCIO
- VRG5
- VIH=1.8V
- VIL=0.6V
- P.157
- P3V3_STBY
- NOPOP
- PVDDQ_CD
- In:P12V_STBY
- Out:
- PCH
- In:P12V_STBY
- Out:
- 6k65£[
- TPS53312
- PWRGD_P3V3_AUX
- TPS53511
- PWRGD_PVCCIO
- 0£[
- PWRGD_P1V5_PCH
- P.153
- EN
- PGOOD
- P.82 - 93
- EN
- PGOOD
- 1k£[
- VIH=2V
- PU44
- (OD)
- 10k£[
- VIH=2V
- PU37
- (OD)
- In:P12V_STBY
- PX3244HDM x4
- Out:
- VIL=0.4V
- VIL=0.4V
- NOPOP
- 10k£[
- P3V3_STBY
- EN
- PGOOD
- PWRGD_PVPP_PVDDQ_CD
- P.177
- P.168
- P1V05_PCH
- PU19
- (OD)
- VIH=0.8V
- VIL=0.4V
- PVCCIN_CPU0_EN
- In:P12V_STBY
- Out:
- 100k£[
- FM_VPP_MEM_ABCD_EN
- CPLD1
- MPQ8636
- PVCCIN_CPU1_EN
- EN
- PGOOD
- PWRGD_P1V05_PCH
- PVCCIN_CPU0
- PU38
- (OD)
- P.138
- CKMNG
- Out
- VIH=2V
- VIL=1.5V
- VIH=2V
- U35
- GATE
- EN
- BMC_READY_N
- P.169
- VIL=0.8V
- P1V8_STBY
- VRG5
- In
- In:P12V_STBY
- PX3746HDN
- Out:
- P.134
- EN
- PGOOD
- PWRGD_PVCCIN_CPU0
- BMC
- PU1
- (OD)
- FM_P3V3_CPLD_EN
- CPLD1
- VIH=0.8V
- 1k£[
- P3V3_STBY
- In:P12V_STBY
- Out:
- 6k65£[
- VIL=0.4V
- P.140
- TPS53312
- PWRGD_P1V8_STBY
- P.138
- PVCCIN_CPU1
- EN
- PU41
- PGOOD
- (OD)
- (3V)
- P3V3_STBY
- VIH=2V
- PWRBTN
- P3V3
- VIL=0.4V
- 10k£[
- In:P12V_STBY
- Out:
- P.172
- PX3746HDN
- PWRGD_PVCCIN_CPU1
- P3V3_STBY
- 100k£[
- EN
- PU7
- PGOOD
- P1V538_STBY
- In:P12V_STBY
- MPQ8636
- Out:
- VIH=0.8V
- (OD)
- P3V3_STBY
- EN
- PGOOD
- PWRGD_P3V3
- VIL=0.4V
- 1k£[
- PU51
- (OD)
- P.144
- 10k£[
- VIH=2V
- In:P1V8_STBY
- Out:
- VIL=1.5V
- P.176
- PWRGD_PCH_PWROK
- TPS74801
- PWRGD_P1V538_STBY
- CPLD1
- EN
- PU40
- PGOOD
- VIH=1.1V
- P.138
- VIL=0.4V
- (LDO)
- P3V3_STBY
- P.173
- PWRGD_DRAMPWRGD_CO
- PWRGD_CPUPWRGD
- P3V3_STBY
- P1V5_PCH
- PCH
- P1V26_STBY
- 10k£[
- In:P1V8_STBY
- Out:
- 10k£[
- TPS74801
- PWRGD_P1V5_PCH
- CPU 0/1
- CPLD1
- In:P1V8_STBY
- Out:
- EN
- PGOOD
- FAB1 REV004 20150320
- TPS74801
- PWRGD_P1V26_STBY
- VIH=1.1V
- PU43
- EN
- PU42
- PGOOD
- VIL=0.4V
- (LDO)
- VIH=1.1V
- P.171
- BMC
- RST_PLTRST_N
- PCH
- PWRGD_SYS_PWROK
- VIL=0.4V
- (LDO)
- P.174
- CPLD1
- CPU & Memory
- Standby Power
- Normal Power
sheet 143
- BIOS SPI SWITCH DIAGRAM
- PCH
- Primary
  SPI Flash
- Quad SPI
- CLK/MISO/MOSI
- CS0#
- U20
- P.82 - 93
- SWITCH
- P.102
- CS#
- U19
- Backup
  SPI Flash
- SWITCH
- CS1#
- Pass-Through SPI Output
- P.102
- P.102
- BMC
- BIOS_SPI_MUX_S
- BMC_SPI_CS
- BMC
  Flash
- Primary SPI
- P.108 - 110
- R375
  10k£[
- R509
  10k£[
- P.109
sheet 144
- UART SEL BLOCK DIAGRAM
- Debug card
- 1K
- UART_SELECT_RC_N
- 10K
- MIDCN2
- COM3_TXD
- Mid-plane
- COM3_RXD
- NOPOP
- P.81
- P.108 - 110
- U46
- DBG1
- COM1_TXD
- System
  UART
- COM1_RXD
- TXD
- Debug
  Header
- SWITCH
- UART
- Debug Card
- BMC
- COM2_TXD
- RXD
- BMC
  UART
- COM2_RXD
- P.114
- P.115
- P3V3_STBY
- NOPOP
- NOPOP
- CH_SELECT0
- CH_SELECT1
- CPLD2
- UART_SELECT
- Logic
- UART_SELECT_R_N
- P.137
- P.115
- UART channel and connection
- Channel
- UART Connection
- 00
- Host console
- 01
- BMC debug console
- 02
- Midplane debug console
sheet 145
- DDR SETTING
- CPU
- DIMM2
- DIMM1
- CS0#
- CS_N0
- CS_N1
- CS1#
- CS_N2/C[0]
- CS2#/C[0]
- CS_N3/C[1]
- CS3#/C[1]
- CS_N4
- CS0#
- CS_N5
- CS1#
- CS_N6/C[3]
- CS2#/C[0]
- CS3#/C[1]
- CS_N7/C[4]
- ODT0
- ODT0
- ODT1
- ODT1
- ODT2
- ODT0
- ODT1
- ODT3
- CKE0
- CKE0
- CKE1
- CKE1
- CKE2
- CKE0
- CKE3
- CKE1
- CLK0P/N
- CK0
- CK1
- CLK2P/N
- CLK1P/N
- CK0
- CLK3P/N
- CK1
- SR/DR
- SR/DR
- LR DIMM/
     RDIMM
- LR DIMM/
     RDIMM
sheet 146
- PERIPHERAL BOARD DIAGRAM
- Debug Card
- 7-Segmant
     Display
- 7-Segmant
     Display
- Com Card
- PCIE TOPOLOGY
- PCIE x24
- Serial
   Port
- CPLD
  EPM3032ATC44-10N
- Select
  Buttom
- Reset
  Buttom
- PCIe Gen3 x16 (32GB/s)
- PCIE (x16, 2A-D)
- QPI0
- QPI
- QPI0
- PCIe Gen3 x8 (16GB/s)
- MEZZ1
  For 10G LAN
- PCIE (x8, 1A-B)
- Debug CONN
- PCIe Gen3 x8 (16GB/s)
- PCIE (x16, 3A-B)
- QPI1
- QPI
- QPI1
- PCIe Gen3 x8 (16GB/s)
- PCIE (x16, 3C-D)
- CPU1
- Layer
- Thickness
- Er
- CPU0
- Mask
- ??
- ??
- Haswell
- L1
- Signal
- 1.7
- Haswell
- Prepreg
- 57.6
- ??
- L2
- Signal
- 1.7
- Mask
- ??
- ??
- Mid-Plane PCIe x8
- Total(mil.)
- 62.3
- Riser Card
- M.2 Adaptor Card
- Mid-Plane Board
- 12.5 V
- PCIE X16 Upper Slot
- Bus Bar Cable
- 2280 SSD
- PCIE X8 Lower Slot
- SATA
- P5V
  Power
- MB1
  POWER CONN1
- PCIE X8
- PCIE X16
- SATA CONN
- USB Golden Finger
- PCIE X24 Golden Finger
- ( Internal )
sheet 147
- HOT PLUG BLOCK DIAGRAM
- Power bus bar
- CM CHOKE
- POWER BOARD
- P12V_MAIN
- FCI power
  connector 1
- P12V_MAIN
- MB
- P12V_FAN1
- MB0_HS_ENABLE
- Hot Swap
  Control
  ADM1278
- SEN+
- FM_PS_EN
- SEN-
- P.129
- FAN0_PWM_CN
- FAN1_PWM_CN
- CPLD
- P12V_STBY
- P.138
- P12V_PCIE_HDD
- FM_P3V3_CPLD_EN
- P3V3
- P.130
- P.176
- FM_PS_EN
- PWRGD_P5V_STBY
- P3V3_STBY
- P.177
- P5V_STBY
- P12V_STBY voltage division
- P5V
- P.175
- P.130
- PWRGD_PS_PWROK
sheet 148
- RESISTOR DEFINITIONS
- SCD1U10V2KX-5GP
  D1U = 0.1uF (if 2D2U is mean 2.2uF)
  10Voltage (if 6D3V is mean 6.3V)
  2 = size 0402, K tolerance
  GP= Green Part (RoHS)
  Wistron C tolerance code as below:
  G=2%
  J=5%
  K=10%
  M=20%
  Wistron C Series/Temp. Characteristics
  N=NPO
  X=X7R/X5R
  Y=Y5V
- 562R2F- GP
  562 = 562 ohm, if 2K2R is mean 2.2K ohm
  2 = size 0402
  F = 1% tolerance
  GP= Green Part (RoHS)
  Wistron RC size code as below:
  1 = 0201
  2= 0402
  3= 0603
  4= 0805
  6= 1206
  Wistron R tolerance code as below:
  F= 1%
  J= 5%
